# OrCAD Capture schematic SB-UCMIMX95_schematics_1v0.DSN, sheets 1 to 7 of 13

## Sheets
1 01. Index and Block Diagram: title: Index and Block Diagram; rev: 1.0
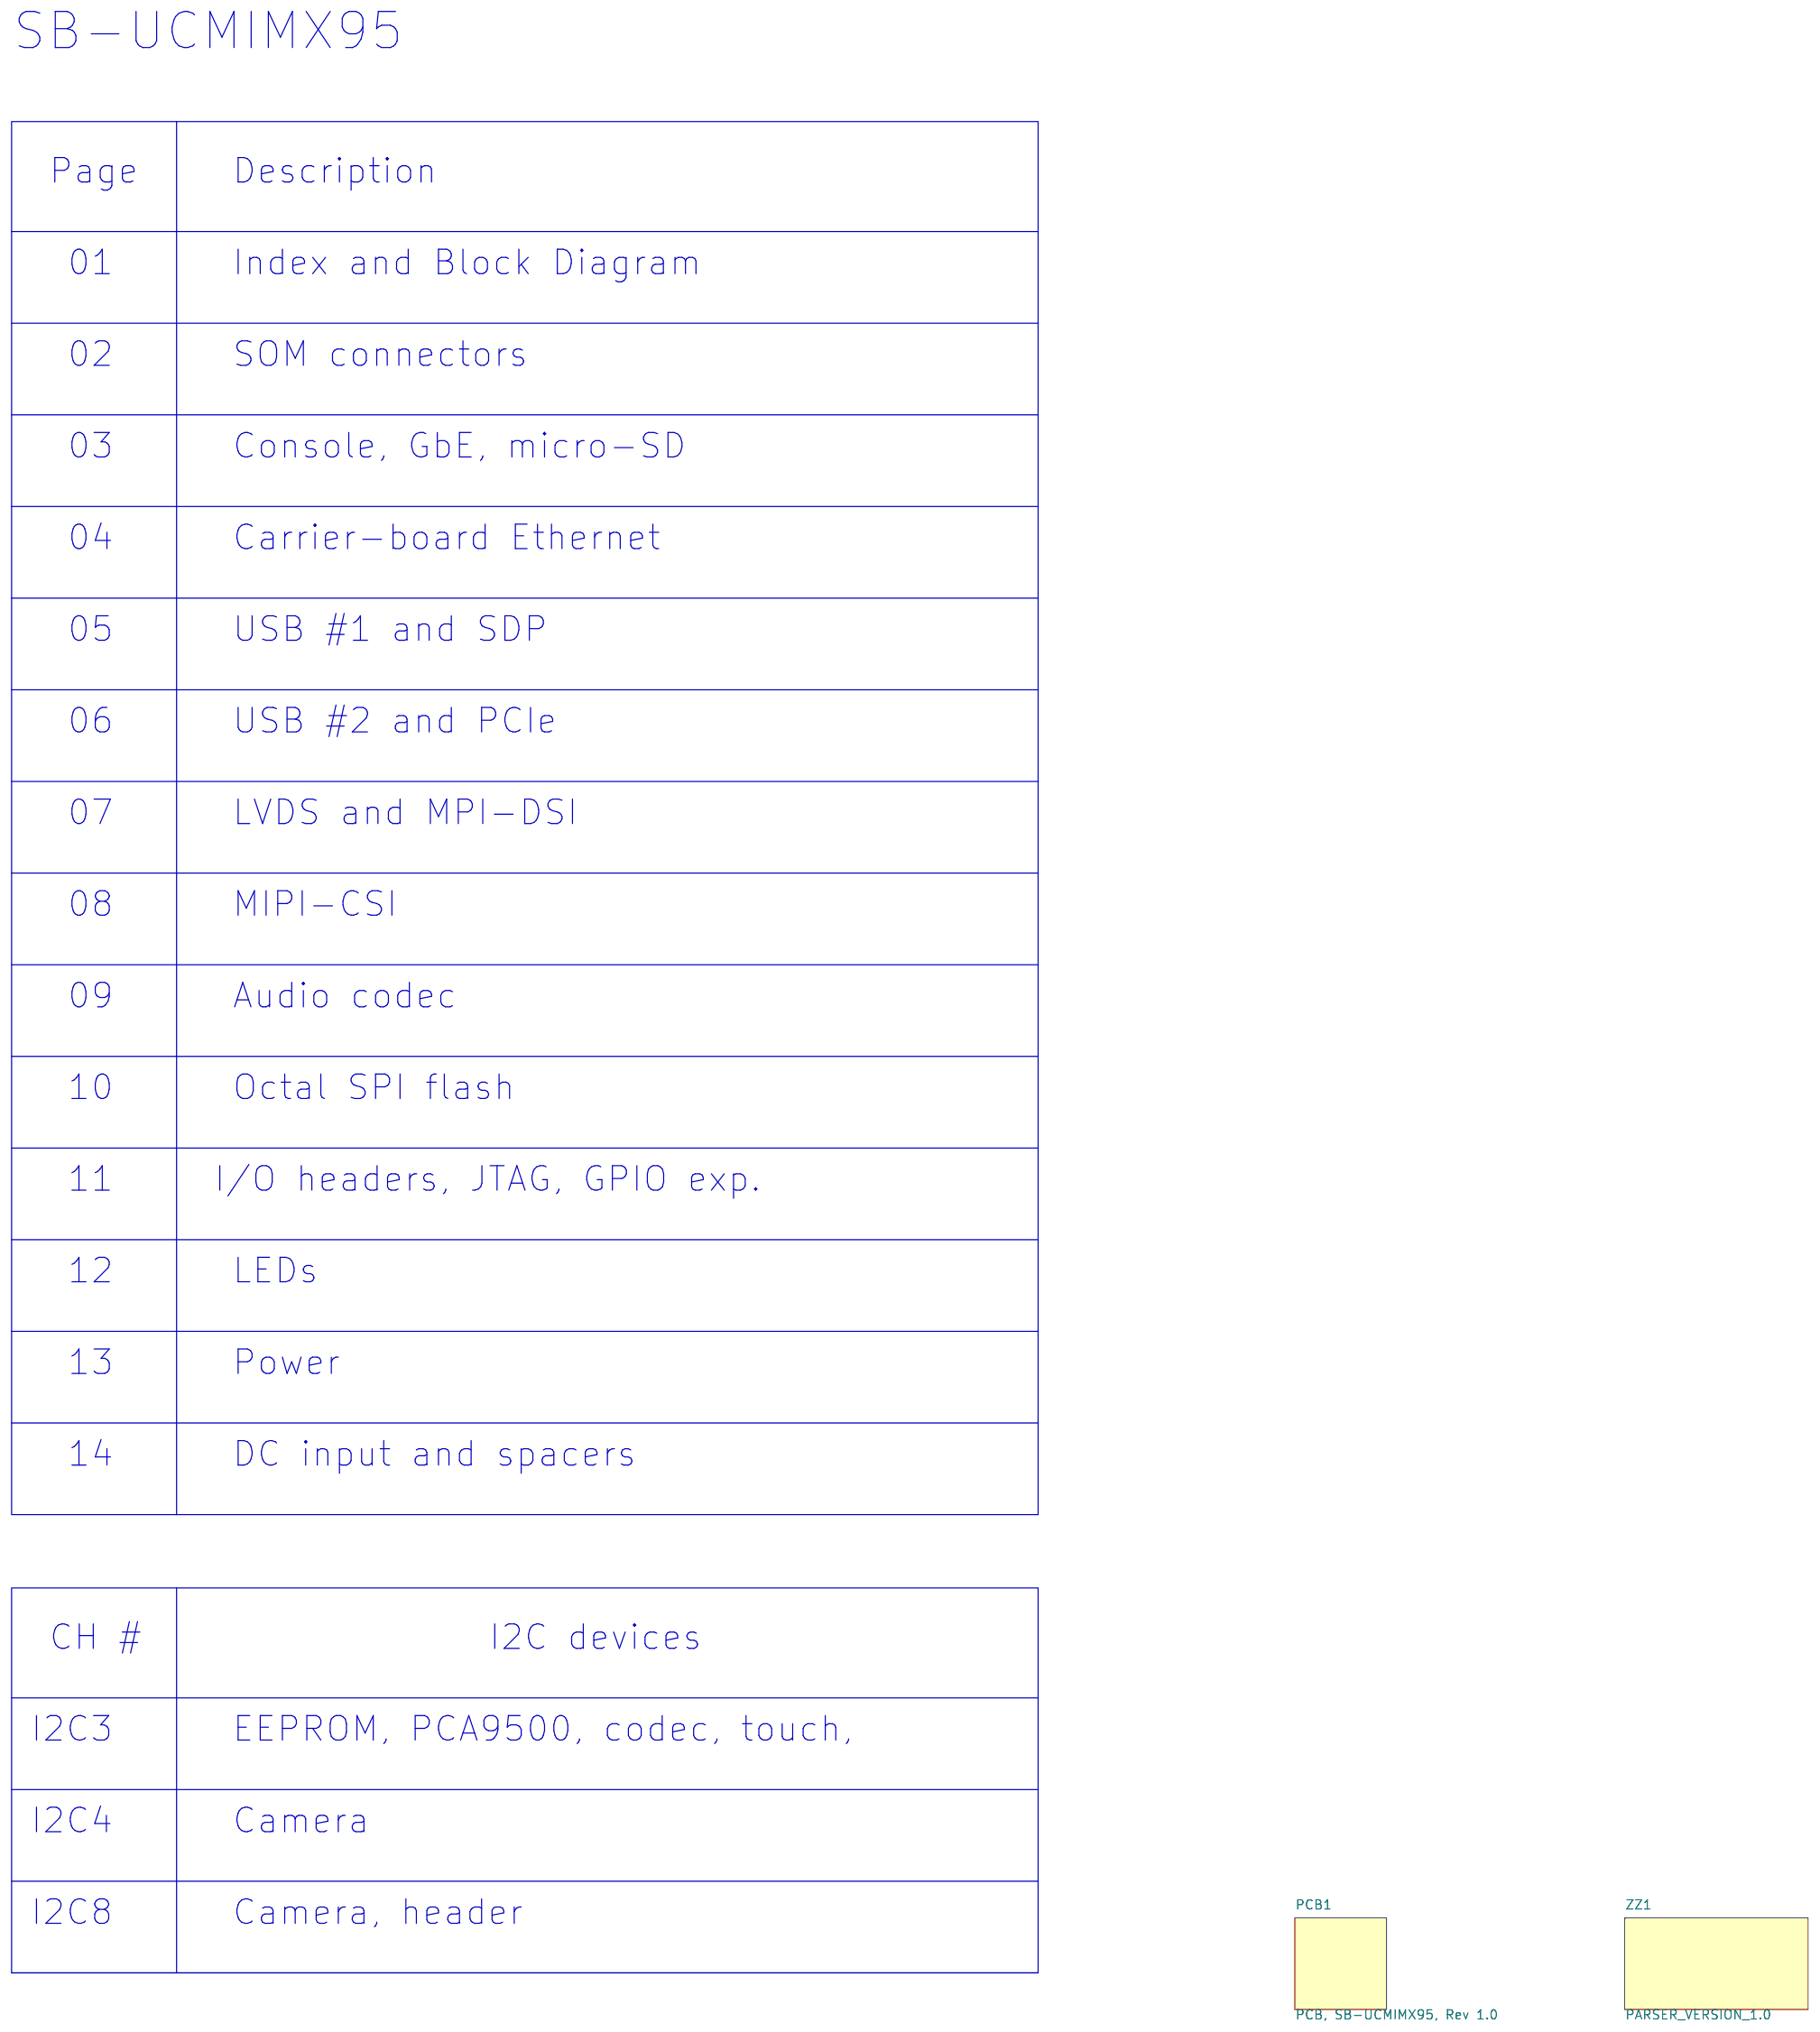
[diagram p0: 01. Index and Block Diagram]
2 02. SOM connectors: size A3; title: SOM connectors
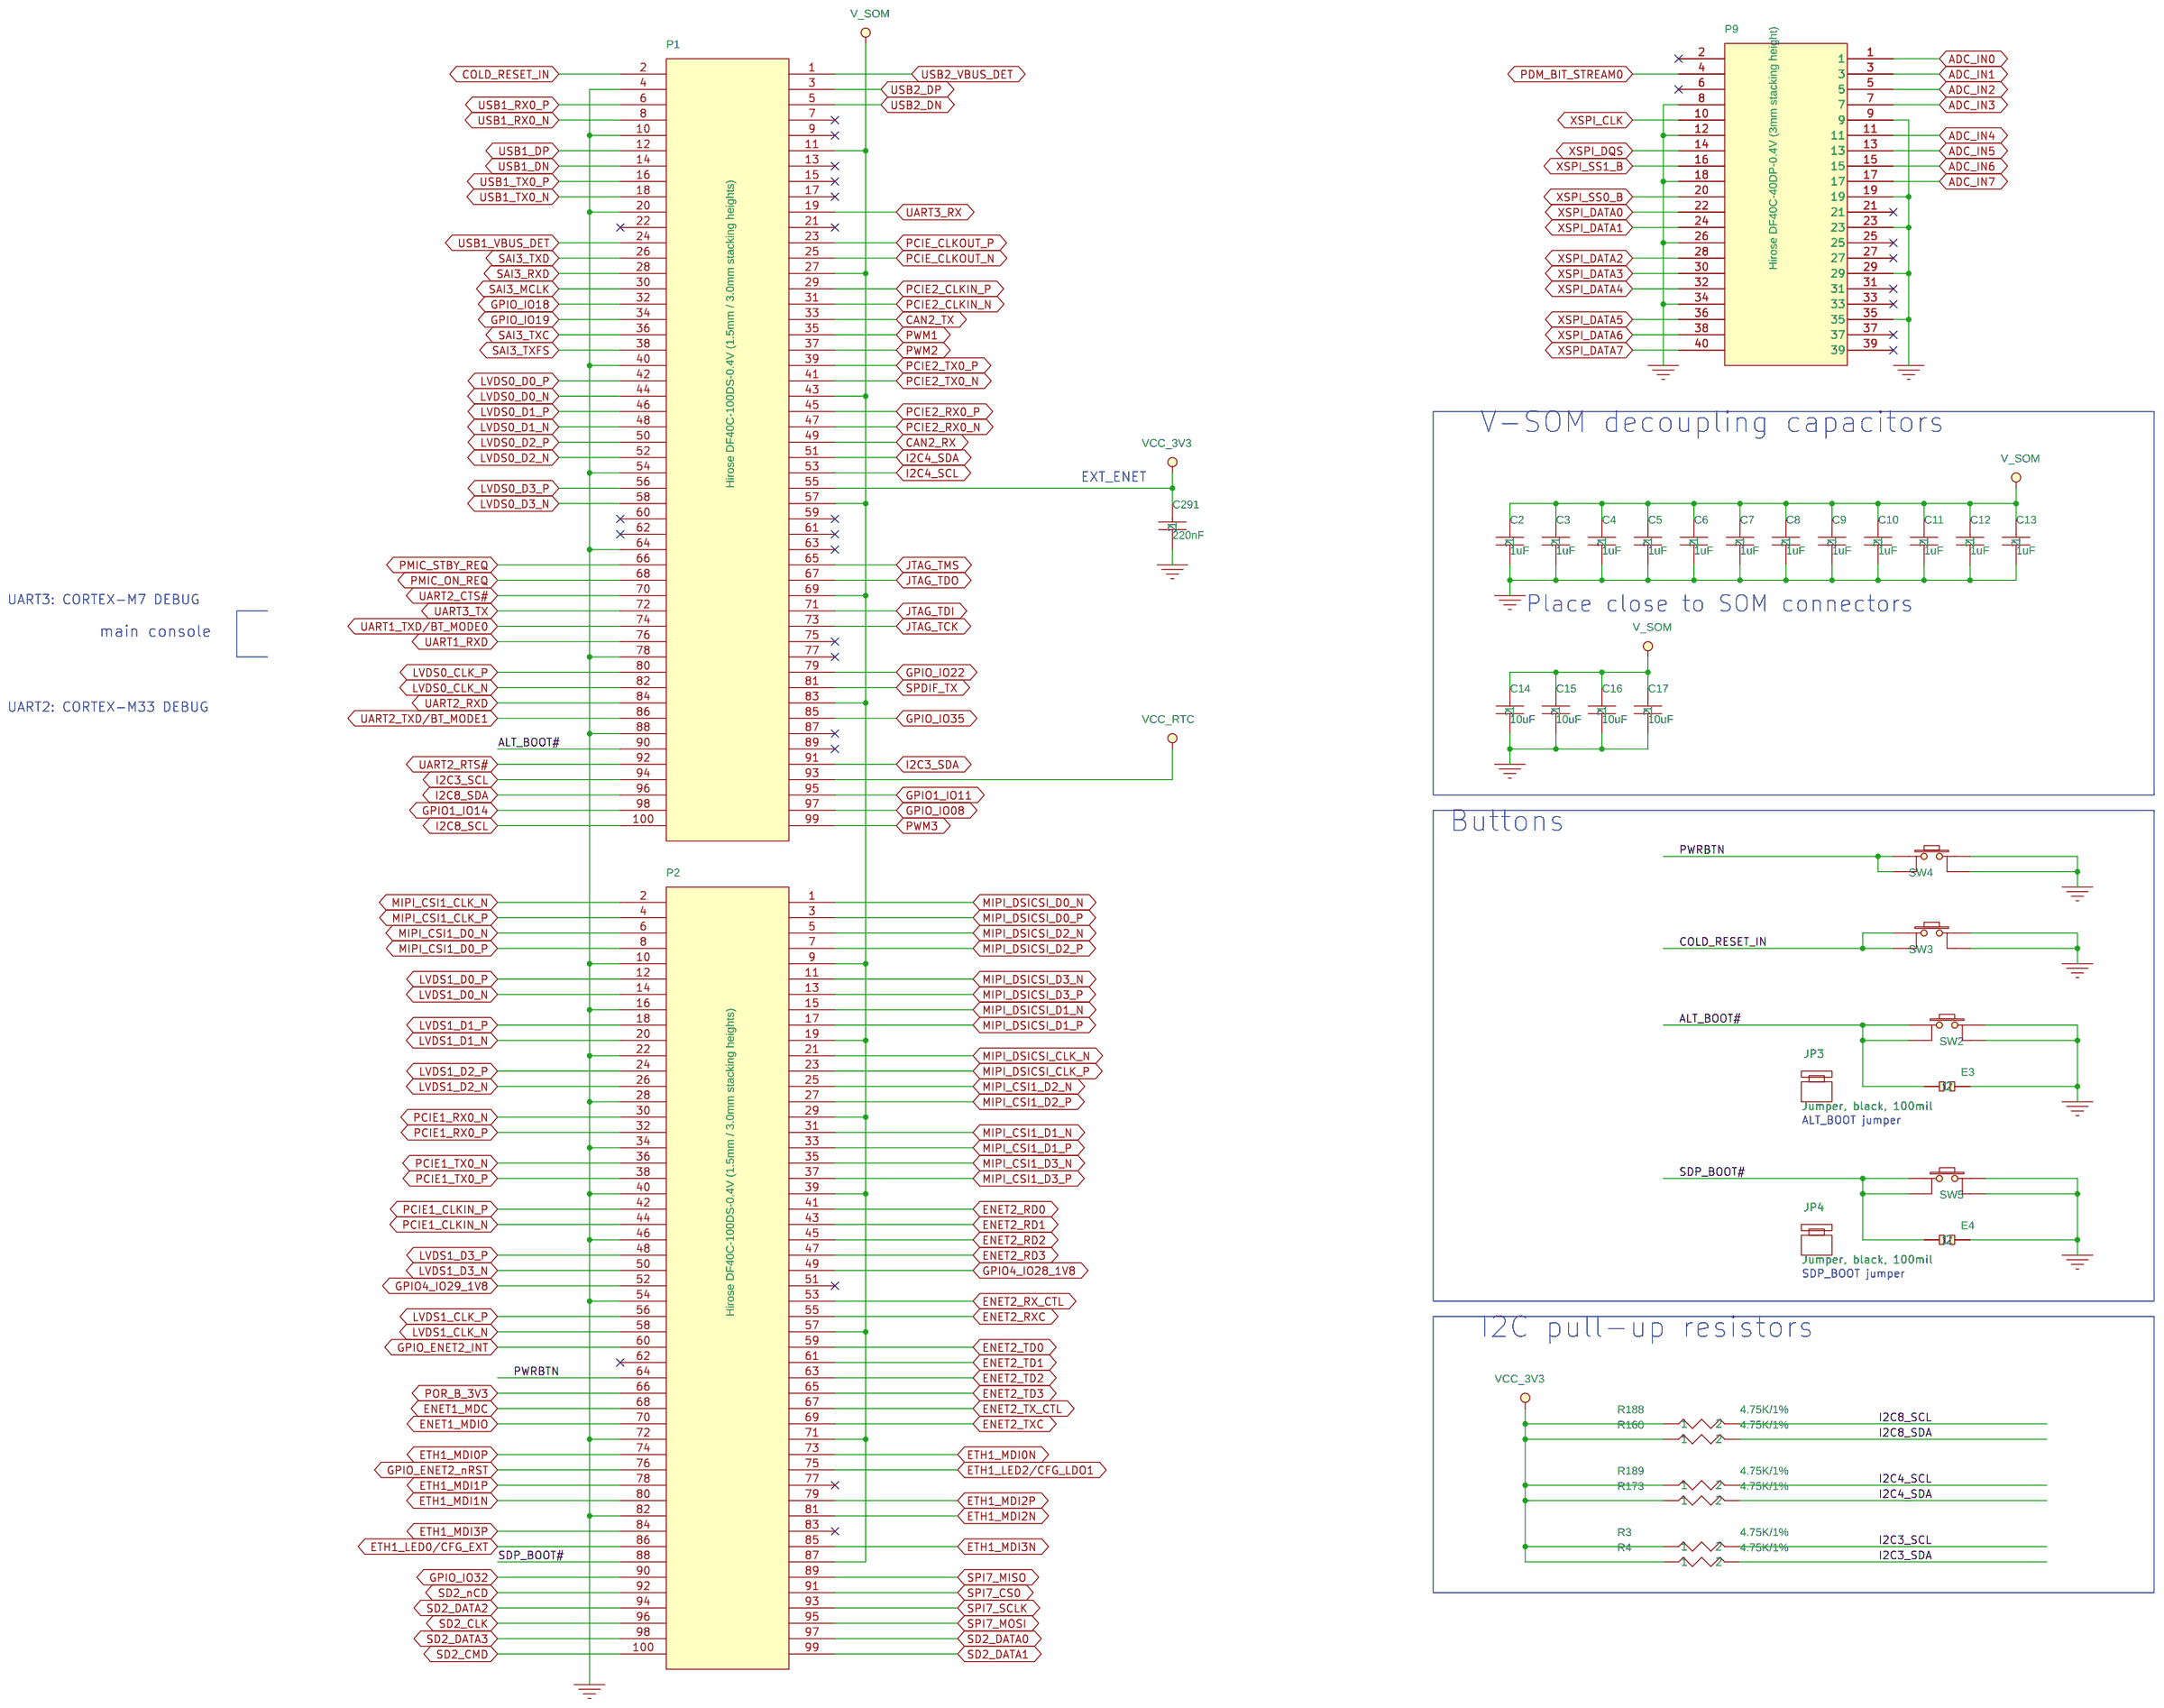
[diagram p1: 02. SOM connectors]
3 03. Console, GbE, micro-SD: size A3; title: Console, GbE, micro-SD
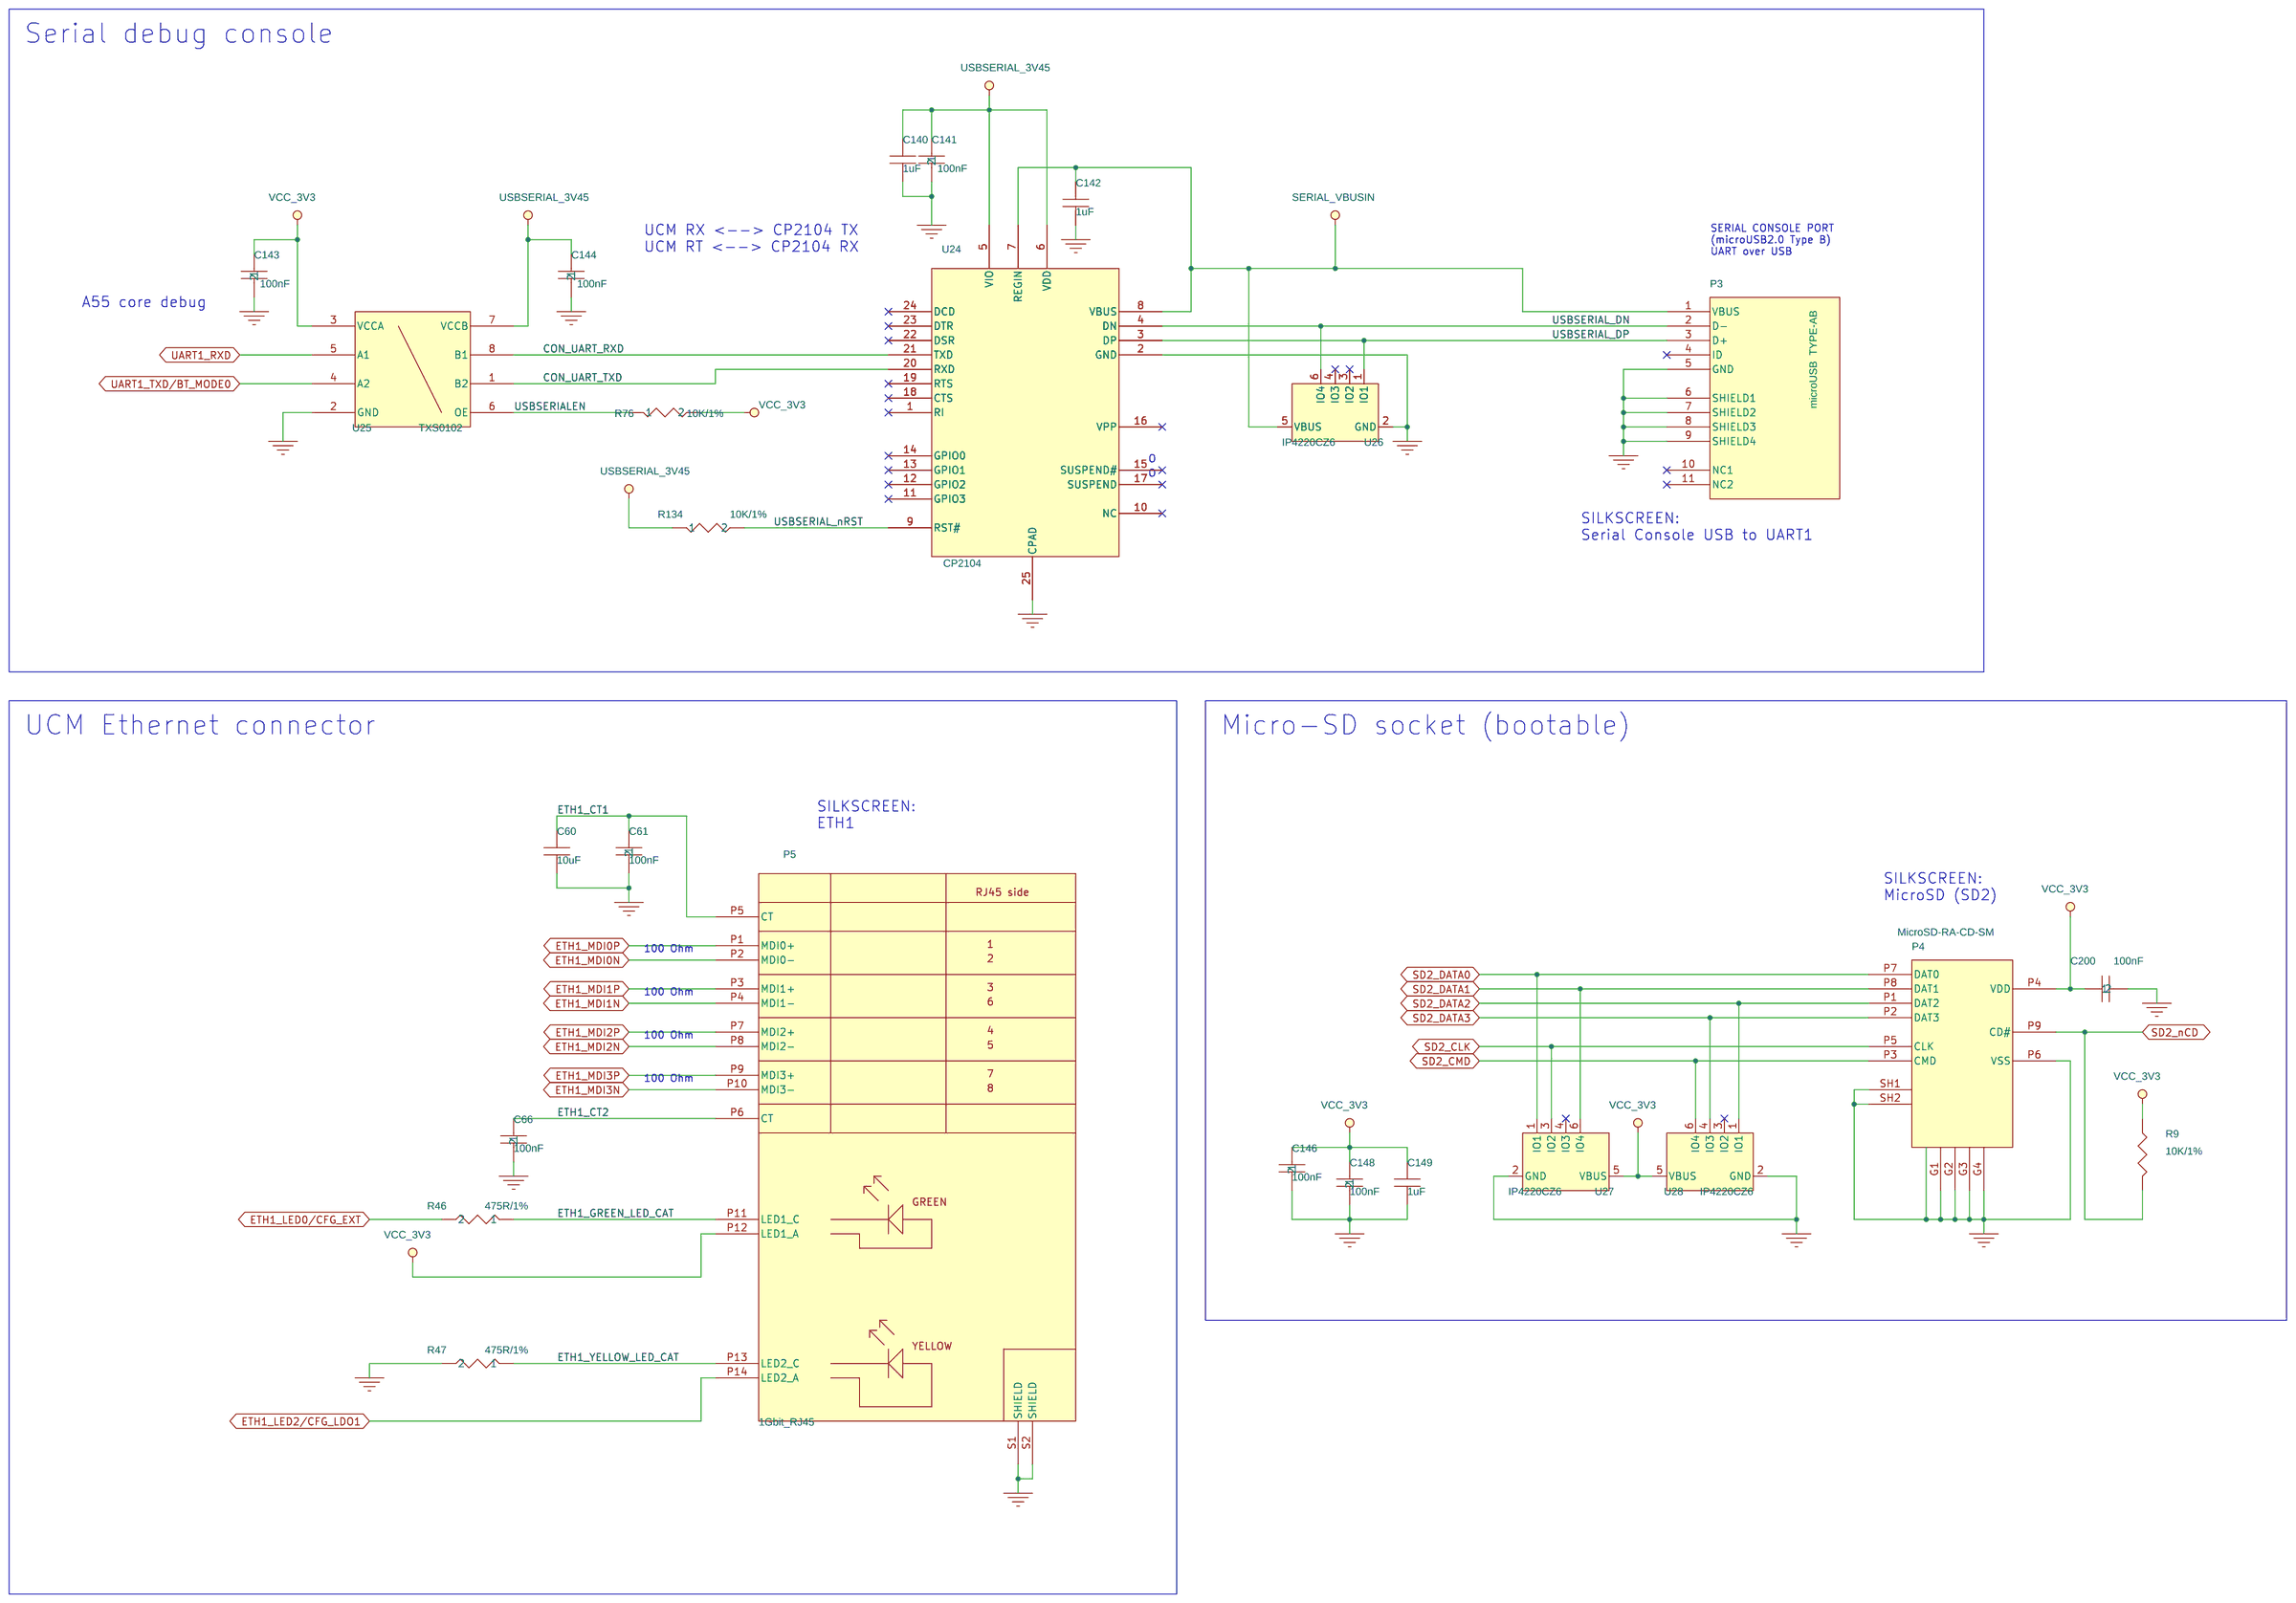
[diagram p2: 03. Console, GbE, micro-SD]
4 04. Carrier-board Ethernet: size A3; title: Carrier-board Ethernet
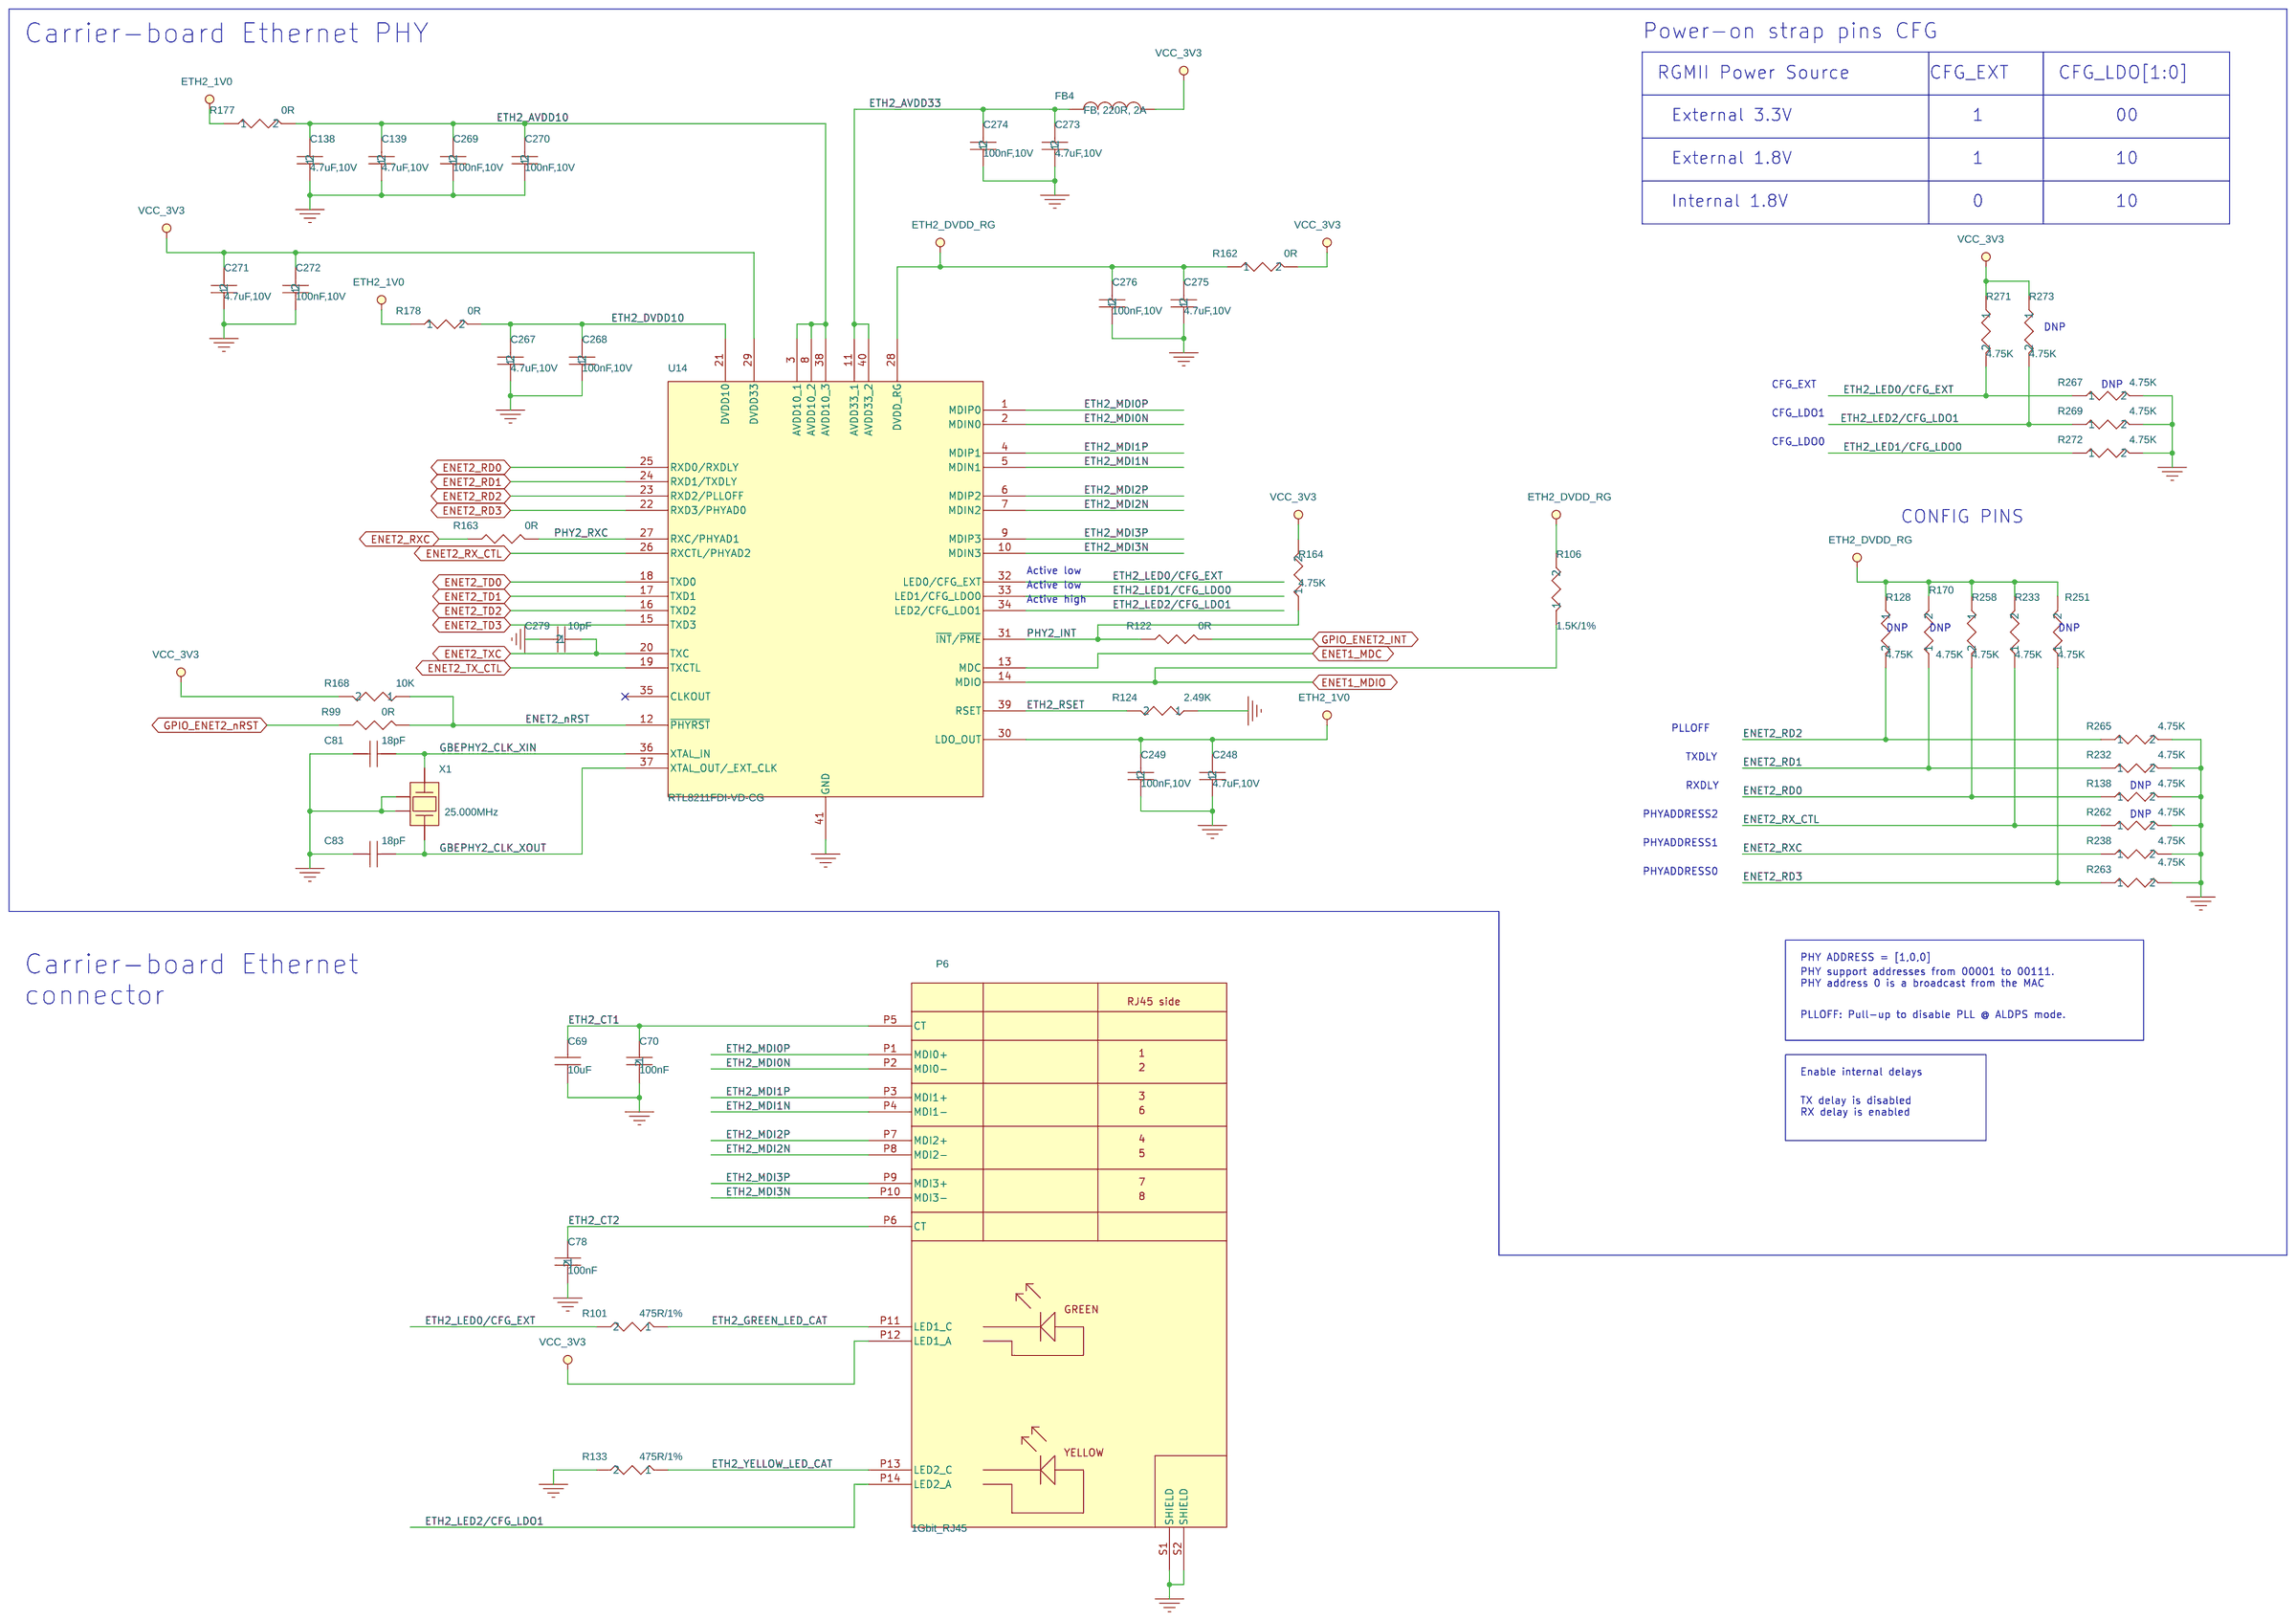
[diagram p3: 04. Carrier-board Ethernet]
5 05. USB #1 and SDP: size A3; title: USB #1 and SDP
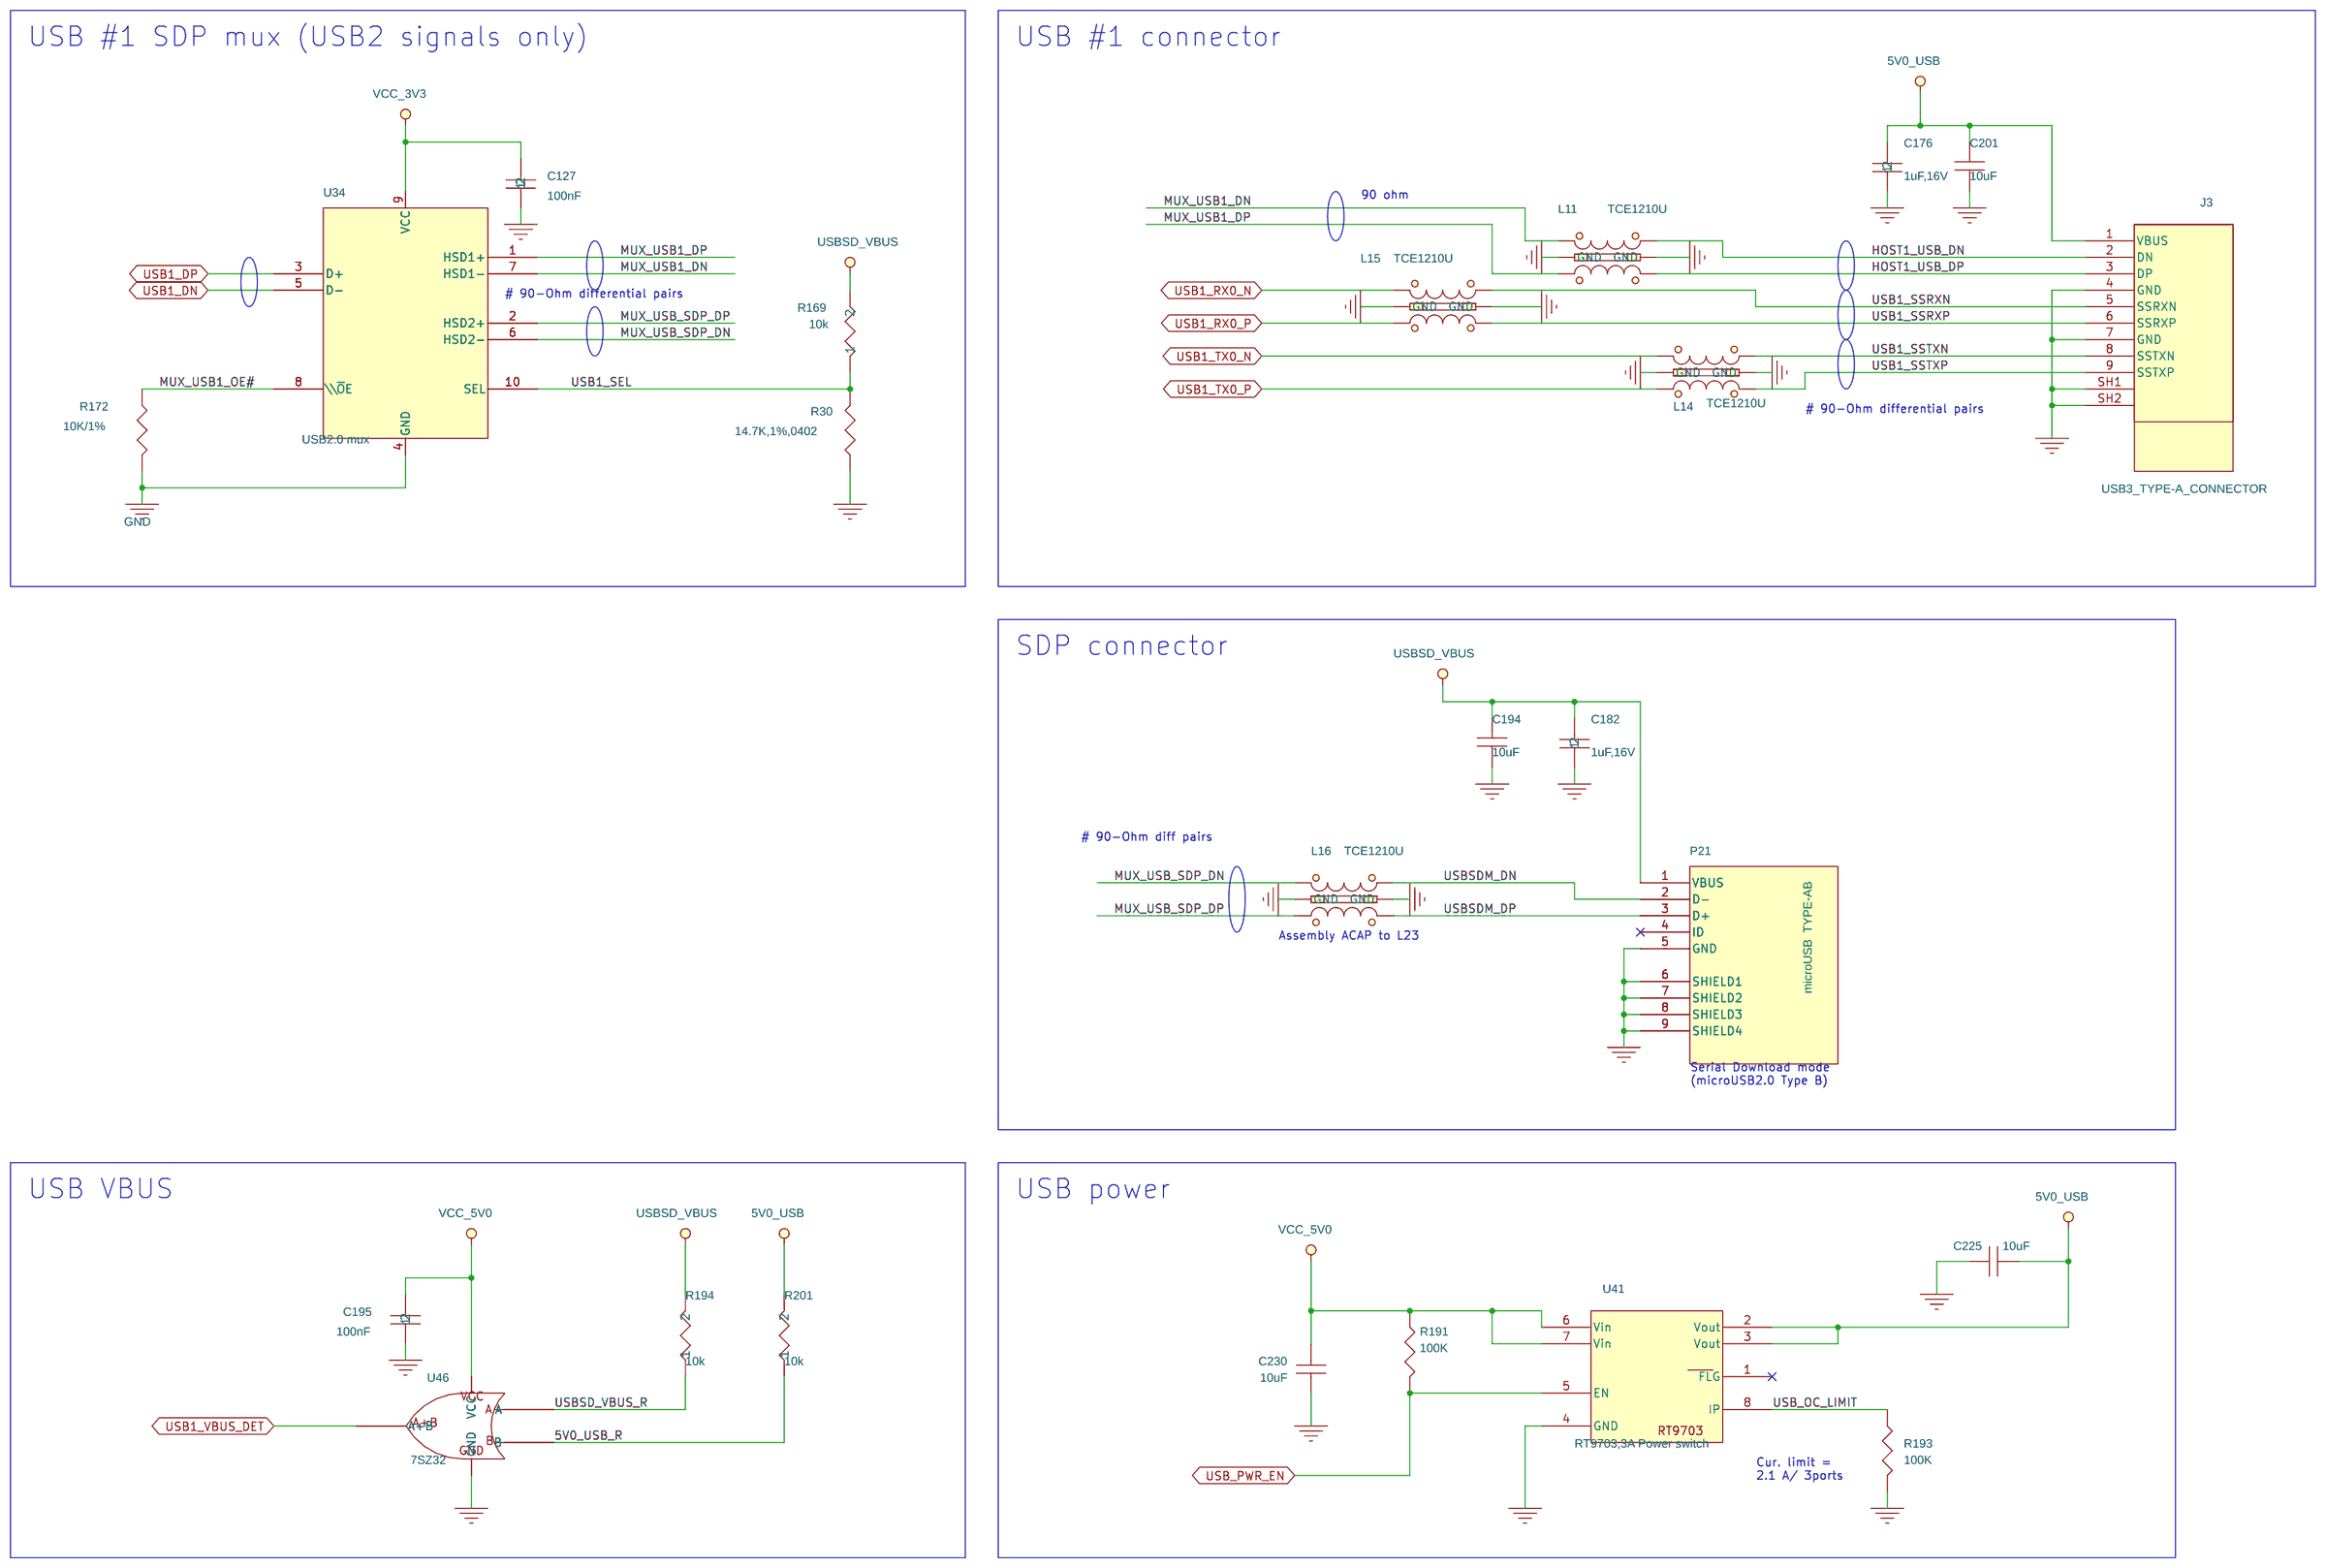
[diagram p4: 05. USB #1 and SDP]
6 06. USB #2 and PCIe: size A3; title: USB #2 and PCIe
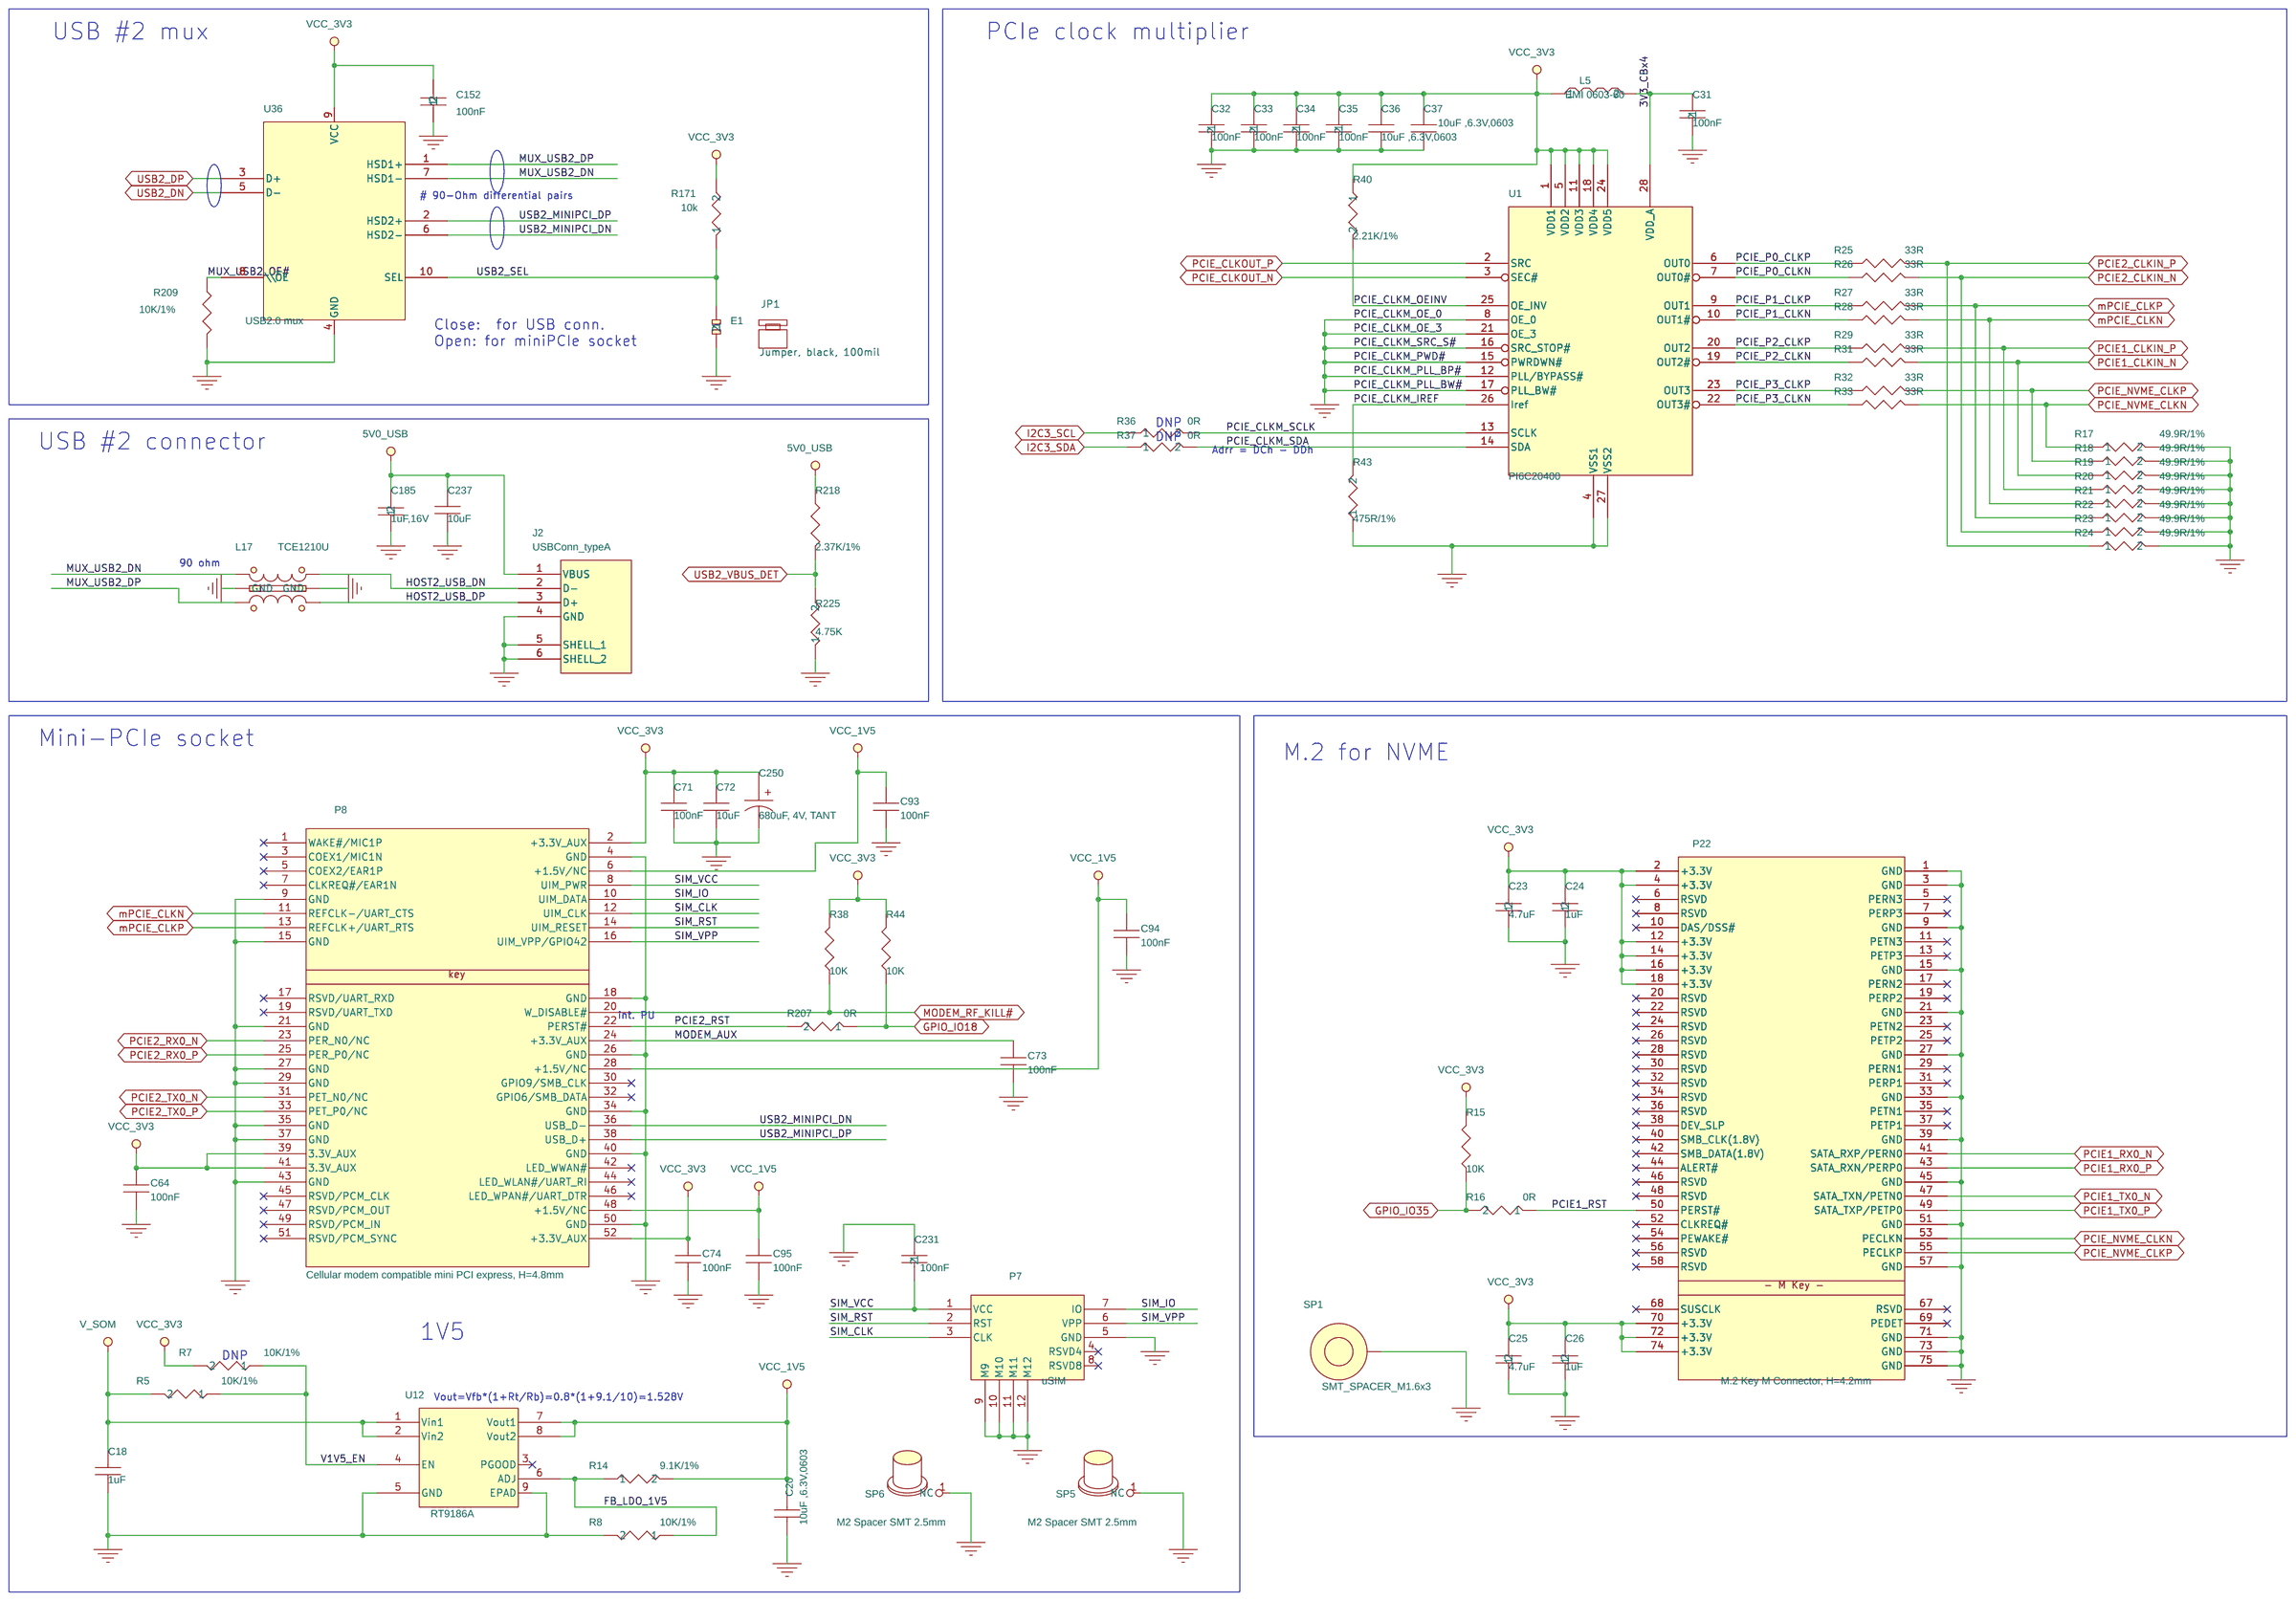
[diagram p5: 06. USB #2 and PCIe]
7 07. LVDS and MIPI-DSI: size A3; title: LVDS and MIPI-DSI
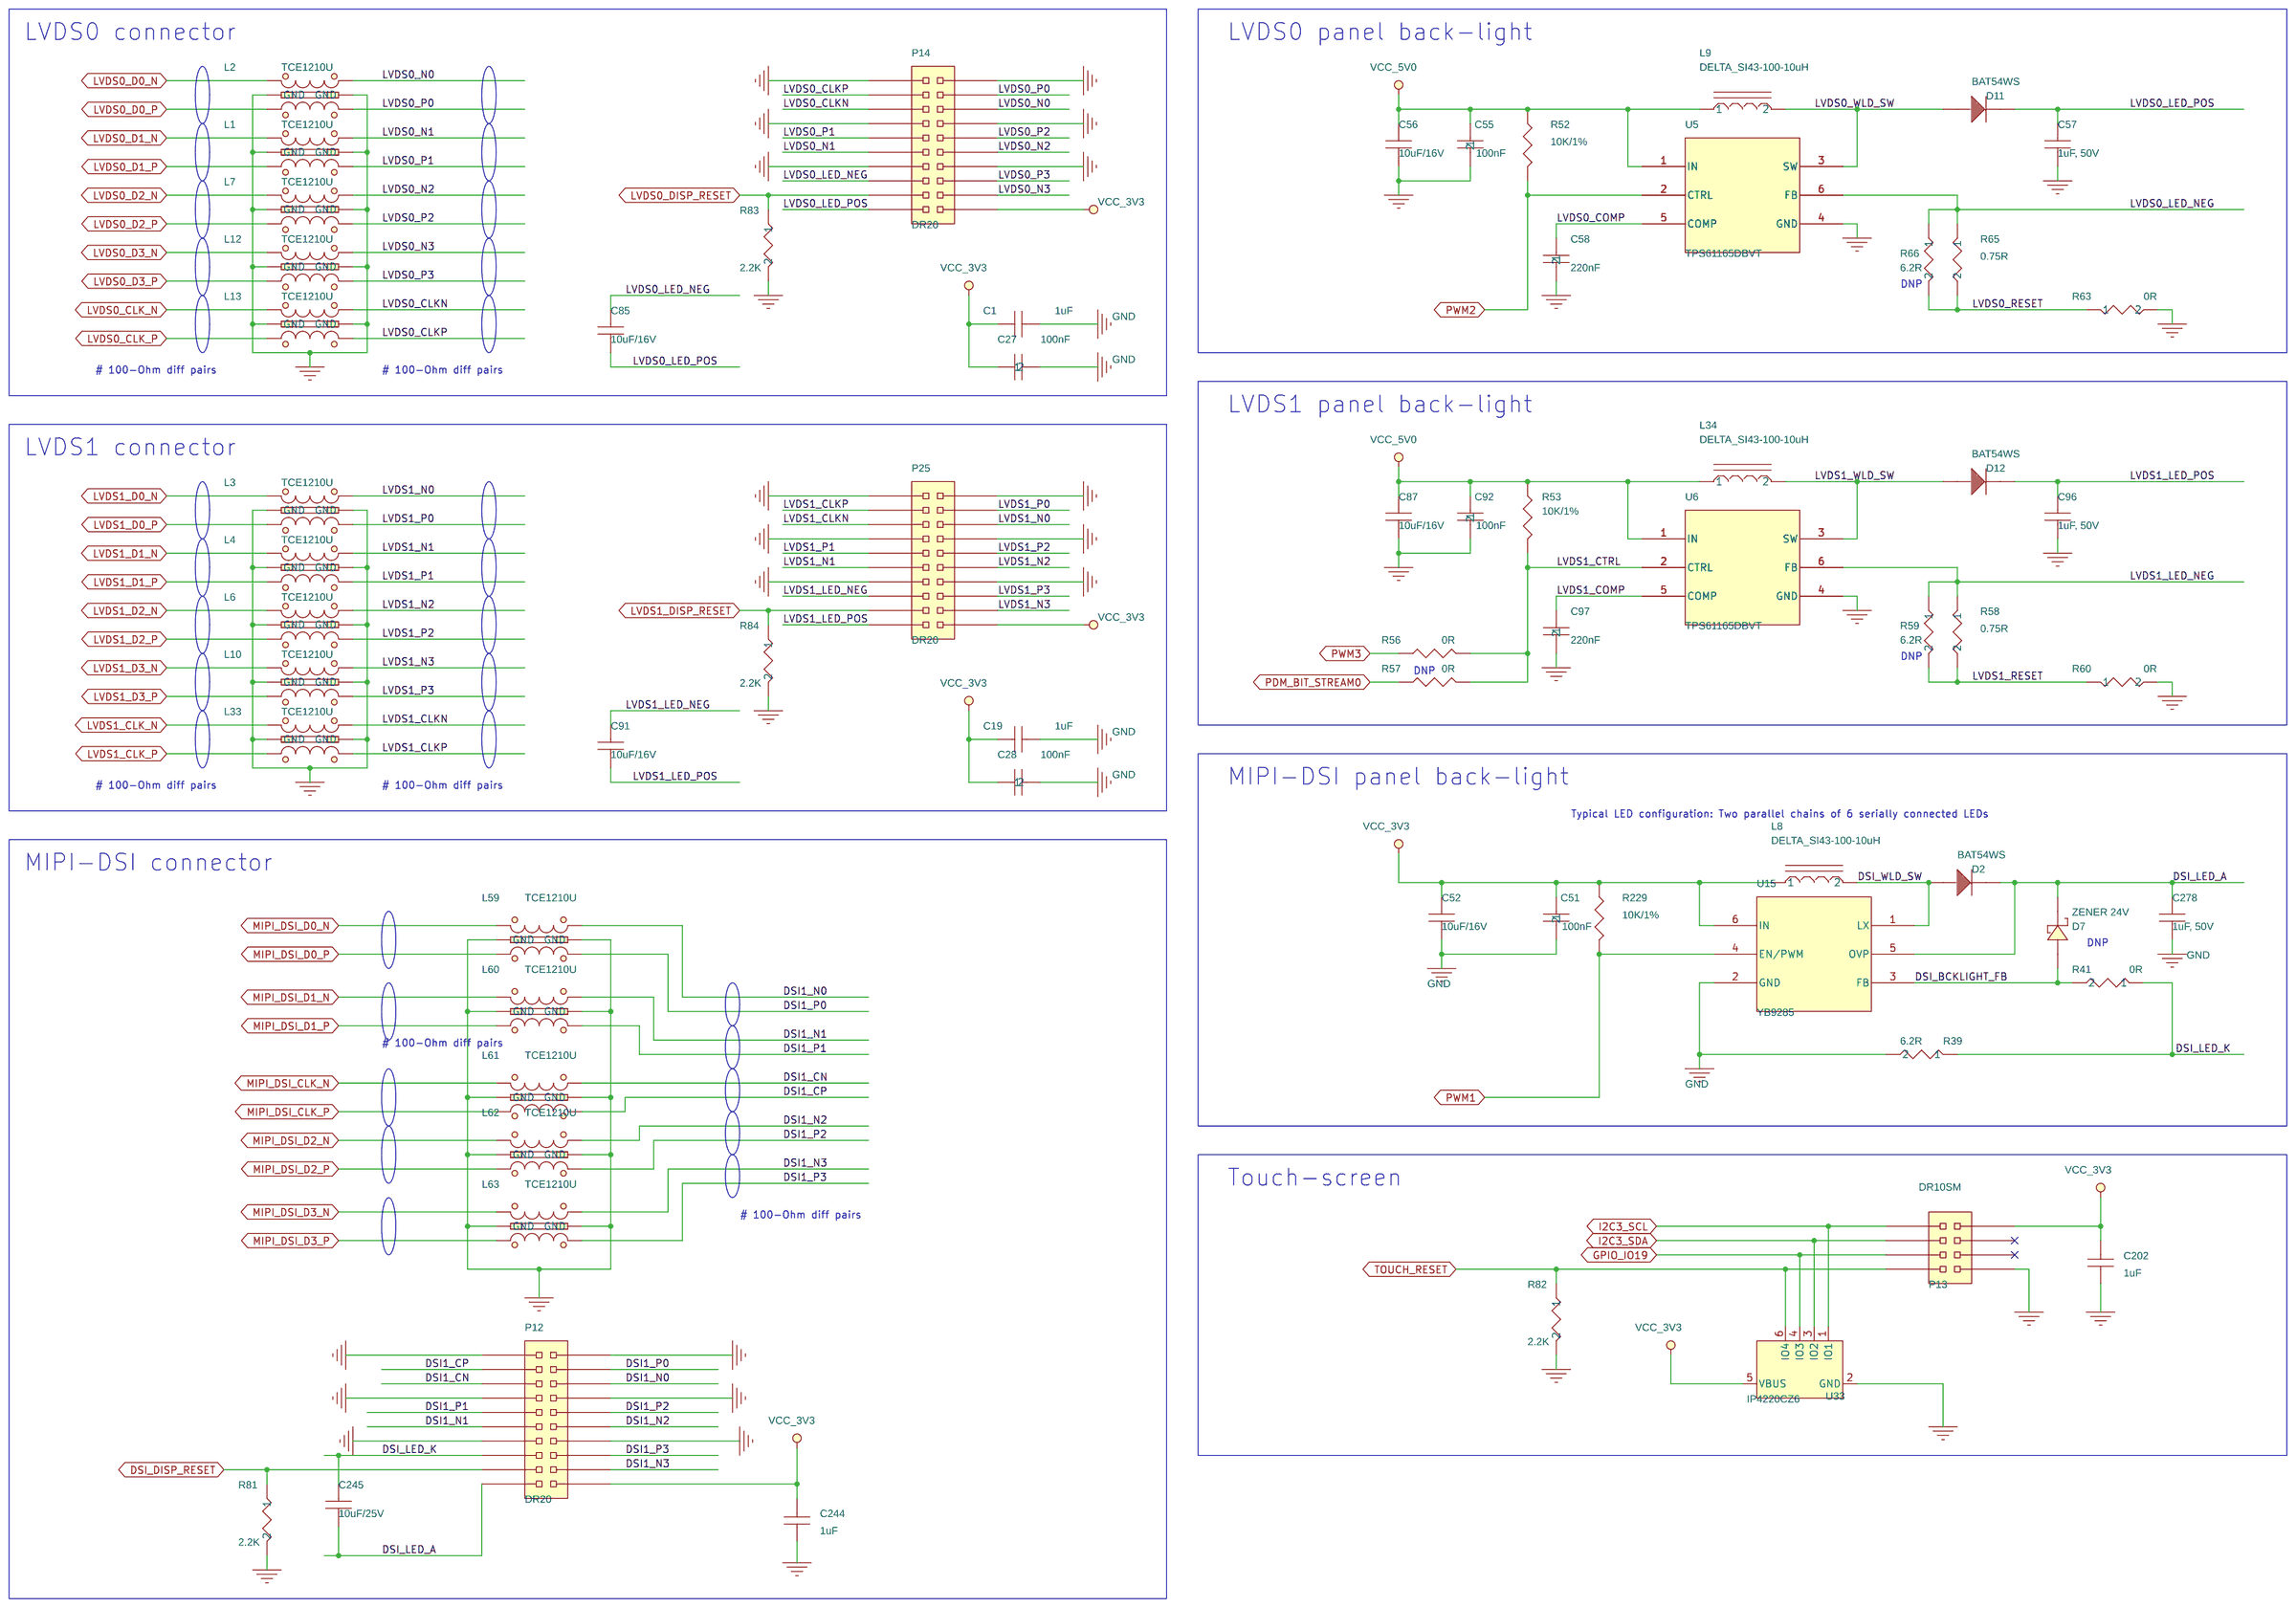
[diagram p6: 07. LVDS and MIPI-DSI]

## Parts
sheet 01. Index and Block Diagram
PCB1  PCB, SB-UCMIMX95, Rev 1.0  [PCB]
ZZ1  PARSER_VERSION_1.0
sheet 02. SOM connectors
C2  1uF  [RC0402]
C3  1uF  [RC0402]
C4  1uF  [RC0402]
C5  1uF  [RC0402]
C6  1uF  [RC0402]
C7  1uF  [RC0402]
C8  1uF  [RC0402]
C9  1uF  [RC0402]
C10  1uF  [RC0402]
C11  1uF  [RC0402]
C12  1uF  [RC0402]
C13  1uF  [RC0402]
C14  10uF  [RC0402]
C15  10uF  [RC0402]
C16  10uF  [RC0402]
C17  10uF  [RC0402]
C291  220nF  [RC0402]
E3  HDR1X2  [1X2THHDR]
E4  HDR1X2  [1X2THHDR]
JP3  Jumper, black, 100mil
JP4  Jumper, black, 100mil
P1  Hirose DF40C-100DS-0.4V (1.5mm / 3.0mm stacking heights)  [B2B04M2X50R]
P2  Hirose DF40C-100DS-0.4V (1.5mm / 3.0mm stacking heights)  [B2B04M2X50R]
P9  Hirose DF40C-40DP-0.4V (3mm stacking height)  [B2B04M2X50P]
R3  4.75K/1%  [RC0402]
R4  4.75K/1%  [RC0402]
R160  4.75K/1%  [RC0402]
R173  4.75K/1%  [RC0402]
R188  4.75K/1%  [RC0402]
R189  4.75K/1%  [RC0402]
SW2  PushB  [TACTSW6x6SM]
SW3  PushB  [TACTSW6x6SM]
SW4  PushB  [TACTSW6x6SM]
SW5  PushB  [TACTSW6x6SM]
sheet 03. Console, GbE, micro-SD
C60  10uF  [RC0603]
C61  100nF  [RC0402]
C66  100nF  [RC0402]
C140  1uF  [RC0402]
C141  100nF  [RC0402]
C142  1uF  [RC0402]
C143  100nF  [RC0402]
C144  100nF  [RC0402]
C146  100nF  [RC0402]
C148  100nF  [RC0402]
C149  1uF  [RC0402]
C200  100nF  [RC0402]
P3  microUSB  TYPE-AB  [MICRO-USB-AB-RA-SM]
P4  MicroSD-RA-CD-SM  [MicroSD-RA-CD-SM]
P5  1Gbit_RJ45  [DUSBRJ-1G]
R9  10K/1%  [RC0402]
R46  475R/1%  [RC0402]
R47  475R/1%  [RC0402]
R76  10K/1%  [RC0402]
R134  10K/1%  [RC0402]
U24  CP2104  [MO-220VGGD-8]
U25  TXS0102  [MO-187DA-8]
U26  IP4220CZ6  [SOT23-6L]
U27  IP4220CZ6  [SOT23-6L]
U28  IP4220CZ6  [SOT23-6L]
sheet 04. Carrier-board Ethernet
C69  10uF  [RC0603]
C70  100nF  [RC0402]
C78  100nF  [RC0402]
C81  18pF  [RC0402]
C83  18pF  [RC0402]
C138  4.7uF,10V  [RC0402]
C139  4.7uF,10V  [RC0402]
C248  4.7uF,10V  [RC0402]
C249  100nF,10V  [RC0402]
C267  4.7uF,10V  [RC0402]
C268  100nF,10V  [RC0402]
C269  100nF,10V  [RC0402]
C270  100nF,10V  [RC0402]
C271  4.7uF,10V  [RC0402]
C272  100nF,10V  [RC0402]
C273  4.7uF,10V  [RC0402]
C274  100nF,10V  [RC0402]
C275  4.7uF,10V  [RC0402]
C276  100nF,10V  [RC0402]
C279  10pF  [RC0402]
FB4  FB, 220R, 2A  [FB0402]
P6  1Gbit_RJ45  [DUSBRJ-1G]
R99  0R  [RC0402]
R101  475R/1%  [RC0402]
R106  1.5K/1%  [RC0402]
R122  0R  [RC0402]
R124  2.49K  [RC0402]
R128  4.75K  [RC0402]
R133  475R/1%  [RC0402]
R138  4.75K  [RC0402]
R162  0R  [RC0402]
R163  0R  [RC0402]
R164  4.75K  [RC0402]
R168  10K  [RC0402]
R170  4.75K  [RC0402]
R177  0R  [RC0402]
R178  0R  [RC0402]
R232  4.75K  [RC0402]
R233  4.75K  [RC0402]
R238  4.75K  [RC0402]
R251  4.75K  [RC0402]
R258  4.75K  [RC0402]
R262  4.75K  [RC0402]
R263  4.75K  [RC0402]
R265  4.75K  [RC0402]
R267  4.75K  [RC0402]
R269  4.75K  [RC0402]
R271  4.75K  [RC0402]
R272  4.75K  [RC0402]
R273  4.75K  [RC0402]
U14  RTL8211FDI-VD-CG  [qfn40_0p4_5x5mm]
X1  25.000MHz  [OSC3225]
sheet 05. USB #1 and SDP
C127  100nF  [RC0402]
C176  1uF,16V  [RC0402]
C182  1uF,16V  [RC0402]
C194  10uF  [C0603-08]
C195  100nF  [RC0402]
C201  10uF  [C0603-08]
C225  10uF  [C0603-08]
C230  10uF  [C0603-08]
J3  USB3_TYPE-A_CONNECTOR  [USB3_TYPEA]
L11  TCE1210U  [EMI1012-ESD]
L14  TCE1210U  [EMI1012-ESD]
L15  TCE1210U  [EMI1012-ESD]
L16  TCE1210U  [EMI1012-ESD]
P21  microUSB  TYPE-AB  [MICRO-USB-AB-RA-SM]
R30  14.7K,1%,0402  [RC0402]
R169  10k  [RC0402]
R172  10K/1%  [RC0402]
R191  100K  [RC0402]
R193  100K  [RC0402]
R194  10k  [RC0402]
R201  10k  [RC0402]
U34  USB2.0 mux  [MO-255U1418E]
U41  RT9703,3A Power switch  [SO-8-150]
U46  7SZ32  [SC70]
sheet 06. USB #2 and PCIe
C18  1uF  [RC0402]
C20  10uF ,6.3V,0603  [C0603-08]
C23  4.7uF  [C0603-08]
C24  1uF  [RC0402]
C25  4.7uF  [C0603-08]
C26  1uF  [RC0402]
C31  100nF  [RC0402]
C32  100nF  [RC0402]
C33  100nF  [RC0402]
C34  100nF  [RC0402]
C35  100nF  [RC0402]
C36  10uF ,6.3V,0603  [RC0603]
C37  10uF ,6.3V,0603  [RC0603]
C64  100nF  [RC0402]
C71  100nF  [RC0402]
C72  10uF  [RC0603]
C73  100nF  [RC0402]
C74  100nF  [RC0402]
C93  100nF  [RC0402]
C94  100nF  [RC0402]
C95  100nF  [RC0402]
C152  100nF  [RC0402]
C185  1uF,16V  [RC0402]
C231  100nF  [RC0402]
C237  10uF  [C0603-08]
C250  680uF, 4V, TANT  [TANT7343]
E1  HDR1X2  [1X2THHDR]
J2  USBConn_typeA  [USB-A-SM]
JP1  Jumper, black, 100mil
L5  EMI 0603-60  [FB0603]
L17  TCE1210U  [EMI1012-ESD]
P7  uSIM  [SKT-MicroSIM6-SM]
P8  Cellular modem compatible mini PCI express, H=4.8mm  [MINIPCIE-4]
P22  M.2 Key M Connector, H=4.2mm  [QFN4x4-32]
R5  10K/1%  [RC0402]
R7  10K/1%  [RC0402]
R8  10K/1%  [RC0402]
R14  9.1K/1%  [RC0402]
R15  10K  [RC0402]
R16  0R  [RC0402]
R17  49.9R/1%  [RC0402]
R18  49.9R/1%  [RC0402]
R19  49.9R/1%  [RC0402]
R20  49.9R/1%  [RC0402]
R21  49.9R/1%  [RC0402]
R22  49.9R/1%  [RC0402]
R23  49.9R/1%  [RC0402]
R24  49.9R/1%  [RC0402]
R25  33R  [RC0402]
R26  33R  [RC0402]
R27  33R  [RC0402]
R28  33R  [RC0402]
R29  33R  [RC0402]
R31  33R  [RC0402]
R32  33R  [RC0402]
R33  33R  [RC0402]
R36  0R  [RC0402]
R37  0R  [RC0402]
R38  10K  [RC0402]
R40  2.21K/1%  [RC0402]
R43  475R/1%  [RC0402]
R44  10K  [RC0402]
R171  10k  [RC0402]
R207  0R  [RC0402]
R209  10K/1%  [RC0402]
R218  2.37K/1%  [RC0402]
R225  4.75K  [RC0402]
SP1  SMT_SPACER_M1.6x3  [MINIPCIE-4-Spacer]
SP5  M2 Spacer SMT 2.5mm  [SpacerM2H4SM]
SP6  M2 Spacer SMT 2.5mm  [SpacerM2H4SM]
U1  PI6C20400  [TSSOP28-6_5-_65]
U12  RT9186A  [DFN3x3-8]
U36  USB2.0 mux  [MO-255U1418E]
sheet 07. LVDS and MIPI-DSI
C1  1uF  [RC0402]
C19  1uF  [RC0402]
C27  100nF  [RC0402]
C28  100nF  [RC0402]
C51  100nF  [RC0402]
C52  10uF/16V  [RC0603]
C55  100nF  [RC0402]
C56  10uF/16V  [RC0603]
C57  1uF, 50V  [RC0603]
C58  220nF  [RC0402]
C85  10uF/16V  [RC0603]
C87  10uF/16V  [RC0603]
C91  10uF/16V  [RC0603]
C92  100nF  [RC0402]
C96  1uF, 50V  [RC0603]
C97  220nF  [RC0402]
C202  1uF  [RC0402]
C244  1uF  [RC0402]
C245  10uF/25V  [RC0603]
C278  1uF, 50V  [RC0603]
D2  BAT54WS  [SOD-323]
D7  ZENER 24V  [SOD-123]
D11  BAT54WS  [SOD-323]
D12  BAT54WS  [SOD-323]
L1  TCE1210U  [EMI1012-ESD]
L2  TCE1210U  [EMI1012-ESD]
L3  TCE1210U  [EMI1012-ESD]
L4  TCE1210U  [EMI1012-ESD]
L6  TCE1210U  [EMI1012-ESD]
L7  TCE1210U  [EMI1012-ESD]
L8  DELTA_SI43-100-10uH  [IND4x4x2_5]
L9  DELTA_SI43-100-10uH  [IND4x4x2_5]
L10  TCE1210U  [EMI1012-ESD]
L12  TCE1210U  [EMI1012-ESD]
L13  TCE1210U  [EMI1012-ESD]
L33  TCE1210U  [EMI1012-ESD]
L34  DELTA_SI43-100-10uH  [IND4x4x2_5]
L59  TCE1210U  [EMI1012-ESD]
L60  TCE1210U  [EMI1012-ESD]
L61  TCE1210U  [EMI1012-ESD]
L62  TCE1210U  [EMI1012-ESD]
L63  TCE1210U  [EMI1012-ESD]
P12  DR20  [2X12THHDR]
P13  DR10SM  [2X4SMHDR]
P14  DR20  [2X12THHDR]
P25  DR20  [2X12THHDR]
R39  6.2R  [RC0402]
R41  0R  [RC0402]
R52  10K/1%  [RC0402]
R53  10K/1%  [RC0402]
R56  0R  [RC0402]
R57  0R  [RC0402]
R58  0.75R  [RC0402]
R59  6.2R  [RC0402]
R60  0R  [RC0402]
R63  0R  [RC0402]
R65  0.75R  [RC0402]
R66  6.2R  [RC0402]
R81  2.2K  [RC0402]
R82  2.2K  [RC0402]
R83  2.2K  [RC0402]
R84  2.2K  [RC0402]
R229  10K/1%  [RC0402]
U5  TPS61165DBVT  [SOT23-6]
U6  TPS61165DBVT  [SOT23-6]
U15  YB9285  [SOT23-6L]
U33  IP4220CZ6  [SOT23-6L]

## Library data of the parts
PCB1 = ATP-FITPC3.rev1.0: CLABCONF0: SB-UCMIMX95; P/N: 188C04550
ZZ1 = PARSER_VERSION_1_1.0: CLABCONF0: DNP
C2 = 100nF,_10V,_X7R,_10%,_0402_1: CLABCONF0: SB-UCMIMX95; P/N: 151B10500S
C3 = 100nF,_10V,_X7R,_10%,_0402_3: CLABCONF0: SB-UCMIMX95; P/N: 151B10500S
C4 = 100nF,_10V,_X7R,_10%,_0402_10: CLABCONF0: SB-UCMIMX95; P/N: 151B10500S
C5 = 100nF,_10V,_X7R,_10%,_0402_4: CLABCONF0: SB-UCMIMX95; P/N: 151B10500S
C6 = 100nF,_10V,_X7R,_10%,_0402_11: CLABCONF0: SB-UCMIMX95; P/N: 151B10500S
C7 = 100nF,_10V,_X7R,_10%,_0402_5: CLABCONF0: SB-UCMIMX95; P/N: 151B10500S
C8 = 100nF,_10V,_X7R,_10%,_0402_8: CLABCONF0: SB-UCMIMX95; P/N: 151B10500S
C9 = 100nF,_10V,_X7R,_10%,_0402_12: CLABCONF0: SB-UCMIMX95; P/N: 151B10500S
C10 = 100nF,_10V,_X7R,_10%,_0402_9: CLABCONF0: SB-UCMIMX95; P/N: 151B10500S
C11 = 100nF,_10V,_X7R,_10%,_0402_7: CLABCONF0: SB-UCMIMX95; P/N: 151B10500S
C12 = 100nF,_10V,_X7R,_10%,_0402_6: CLABCONF0: SB-UCMIMX95; P/N: 151B10500S
C13 = 100nF,_10V,_X7R,_10%,_0402: CLABCONF0: SB-UCMIMX95; P/N: 151B10500S
C14 = 10uF_10V_20%_0402: CLABCONF0: SB-UCMIMX95
C15 = 10uF_10V_20%_0402_3: CLABCONF0: SB-UCMIMX95
C16 = 10uF_10V_20%_0402_2: CLABCONF0: SB-UCMIMX95
C17 = 10uF_10V_20%_0402_1: CLABCONF0: SB-UCMIMX95
C291 = 100nF,_10V,_X7R,_10%,_0402_2: CLABCONF0: SB-UCMIMX95; P/N: 151C22400S
E3 = HDR_1x2_100MIL_TH_JUMPER_1: CLABCONF0: SB-UCMIMX95
E1 E4 = HDR_1x2_100MIL_TH_JUMPER: CLABCONF0: SB-UCMIMX95
JP1 JP3 JP4 = Jumper,_black,_100mil: CLABCONF0: SB-UCMIMX95
P1 P2 = Hirose_DF40C-100DP-0.4V: CLABCONF0: SB-UCMIMX95; P/N: 182K10005S
P9 = Hirose_DF40C-100DP-0_1.4V: CLABCONF0: SB-UCMIMX95; P/N: 182K04005S
R3 = 4_0.75K,1%,0402,1_16W: CLABCONF0: SB-UCMIMX95
R4 = 4_0.75K,1%,0402,1_16W_3: CLABCONF0: SB-UCMIMX95
R160 = 4_0.75K,1%,0402,1_16W_5: CLABCONF0: SB-UCMIMX95
R173 = 4_0.75K,1%,0402,1_16W_1: CLABCONF0: SB-UCMIMX95
R188 = 4_0.75K,1%,0402,1_16W_2: CLABCONF0: SB-UCMIMX95
R189 = 4_0.75K,1%,0402,1_16W_4: CLABCONF0: SB-UCMIMX95
SW2-SW5 = TACT_SW_6x6mm_SMT: CLABCONF0: SB-UCMIMX95
C60 C69 = Cap.,10uF,6.3V,0603,X5R: CLABCONF0: SB-UCMIMX95; P/N: 151B10600S
C61 = 100nF,_10V,_X7R,_10%,_0402_7: CLABCONF0: SB-UCMIMX95
C51 C66 = 100nF,_10V,_X7R,_10%,_0402_6: CLABCONF0: SB-UCMIMX95
C1 C18 C19 C140 C142 C149 C202 C244 = 1uF,X5R,6.3V,0402: CLABCONF0: SB-UCMIMX95
C78 C141 = 100nF,_10V,_X7R,_10%,_0402_1: CLABCONF0: SB-UCMIMX95
C70 C92 C143 = 100nF,_10V,_X7R,_10%,_0402: CLABCONF0: SB-UCMIMX95
C144 = 100nF,_10V,_X7R,_10%,_0402_4: CLABCONF0: SB-UCMIMX95
C28 C146 = 100nF,_10V,_X7R,_10%,_0402_5: CLABCONF0: SB-UCMIMX95
C55 C148 = 100nF,_10V,_X7R,_10%,_0402_3: CLABCONF0: SB-UCMIMX95
C27 C200 C231 = 100nF,_10V,_X7R,_10%,_0402_2: CLABCONF0: SB-UCMIMX95
P3 = Conn_1.,_Micro-USB,_B-Type: CLABCONF0: SB-UCMIMX95; P/N: 180K00501S
P4 = microSD_push-pull: CLABCONF0: SB-UCMIMX95; P/N: 182K01300S
P5 P6 = Con_0.,1GBit_RJ45,_short: CLABCONF0: SB-UCMIMX95
R9 R172 R229 = 10K,1%,0402,1_16W_0: CLABCONF0: SB-UCMIMX95
R43 R46 R133 = 475R_1%,_0402: CLABCONF0: SB-UCMIMX95
R47 R101 = 475R_1%,_0402_1: CLABCONF0: SB-UCMIMX95
R5 R76 = 10K,1%,0402,1_16W_1: CLABCONF0: SB-UCMIMX95
R134 = 10K,1%,0402,1_16W: CLABCONF0: SB-UCMIMX95
U24 = CP2104_1: CLABCONF0: SB-UCMIMX95; P/N: 116A00140S
U25 = TXS0102_0: CLABCONF0: SB-UCMIMX95; P/N: 116A01020S
U26-U28 U33 = IP4220CZ6_0: CLABCONF0: SB-UCMIMX95
C81 C83 = 27pF,_50V,_X7R,_10%,_0402: CLABCONF0: SB-UCMIMX95; P/N: 151D18000S
C138 = 15pF,_50V,_NPO,_5%,_0402_9: CLABCONF0: SB-UCMIMX95; P/N: 151B47500S
C139 = 15pF,_50V,_NPO,_5%,_0402_5: CLABCONF0: SB-UCMIMX95; P/N: 151B47500S
C248 = 15pF,_50V,_NPO,_5%,_0402: CLABCONF0: SB-UCMIMX95; P/N: 151B47500S
C249 = 15pF,_50V,_NPO,_5%,_0402_2: CLABCONF0: SB-UCMIMX95; P/N: 151B10400S
C267 = 15pF,_50V,_NPO,_5%,_0402_13: CLABCONF0: SB-UCMIMX95; P/N: 151B47500S
C268 = 15pF,_50V,_NPO,_5%,_0402_12: CLABCONF0: SB-UCMIMX95; P/N: 151B10400S
C269 = 15pF,_50V,_NPO,_5%,_0402_8: CLABCONF0: SB-UCMIMX95; P/N: 151B10400S
C270 = 15pF,_50V,_NPO,_5%,_0402_7: CLABCONF0: SB-UCMIMX95; P/N: 151B10400S
C271 = 15pF,_50V,_NPO,_5%,_0402_6: CLABCONF0: SB-UCMIMX95; P/N: 151B47500S
C272 = 15pF,_50V,_NPO,_5%,_0402_14: CLABCONF0: SB-UCMIMX95; P/N: 151B10400S
C273 = 15pF,_50V,_NPO,_5%,_0402_4: CLABCONF0: SB-UCMIMX95; P/N: 151B47500S
C274 = 15pF,_50V,_NPO,_5%,_0402_11: CLABCONF0: SB-UCMIMX95; P/N: 151B10400S
C275 = 15pF,_50V,_NPO,_5%,_0402_1: CLABCONF0: SB-UCMIMX95; P/N: 151B47500S
C276 = 15pF,_50V,_NPO,_5%,_0402_10: CLABCONF0: SB-UCMIMX95; P/N: 151B10400S
C279 = 15pF,_50V,_NPO,_5%,_0402_3: CLABCONF0: DNP; P/N: 151D10000S
FB4 = Ferrite_bead_,_120_Ohm@3A: CLABCONF0: SB-UCMIMX95; P/N: 147D22101S
R56 R99 = 0R,_0402_0_1: CLABCONF0: SB-UCMIMX95
R106 = 1.5K_1%,_0402: CLABCONF0: SB-UCMIMX95
R122 = 0R,_0402_0: CLABCONF0: SB-UCMIMX95
R124 = 1M_,5%,_0402_2: CLABCONF0: SB-UCMIMX95; P/N: 161C24911S
R128 = 4.75K,1%,0402,1_16W_7: CLABCONF0: DNP
R138 = 4.75K,1%,0402,1_16W_4: CLABCONF0: DNP
R162 = 0R,_0402_2: CLABCONF0: SB-UCMIMX95
R163 = 0R,_0402_0_2: CLABCONF0: SB-UCMIMX95
R164 R225 = 1M_,5%,_0402: CLABCONF0: SB-UCMIMX95; P/N: 161C47511S
R168 R171 R194 = 1M_,5%,_0402_1: CLABCONF0: SB-UCMIMX95; P/N: 161C10021S
R170 = 4.75K,1%,0402,1_16W_1: CLABCONF0: DNP
R177 R207 = 0R,_0402_1: CLABCONF0: SB-UCMIMX95
R41 R178 = 0R,_0402: CLABCONF0: SB-UCMIMX95
R232 = 4.75K,1%,0402,1_16W: CLABCONF0: SB-UCMIMX95
R233 = 4.75K,1%,0402,1_16W_2: CLABCONF0: SB-UCMIMX95
R238 = 4.75K,1%,0402,1_16W_15: CLABCONF0: SB-UCMIMX95
R251 = 4.75K,1%,0402,1_16W_12: CLABCONF0: DNP
R258 = 4.75K,1%,0402,1_16W_13: CLABCONF0: SB-UCMIMX95
R262 = 4.75K,1%,0402,1_16W_8: CLABCONF0: DNP
R263 = 4.75K,1%,0402,1_16W_14: CLABCONF0: SB-UCMIMX95
R265 = 4.75K,1%,0402,1_16W_10: CLABCONF0: SB-UCMIMX95
R267 = 4.75K,1%,0402,1_16W_9: CLABCONF0: DNP
R269 = 4.75K,1%,0402,1_16W_11: CLABCONF0: SB-UCMIMX95
R271 = 4.75K,1%,0402,1_16W_6: CLABCONF0: SB-UCMIMX95
R272 = 4.75K,1%,0402,1_16W_3: CLABCONF0: SB-UCMIMX95
R273 = 4.75K,1%,0402,1_16W_5: CLABCONF0: DNP
U14 = RTL8211FDI-40P_A_0: IC XCVR ETH INTEGRATED 10/100/1000MBPS RGMII 3.3V/2.5V/1.8V QFN40; 3D_Mechanical_Footprint_File: http://fcl.am.freescale.net/ALLEGRO/step/qfn40_0p4_5x5mm.STEP; AGILE_PN: TMP-CIP-10596; CAD_APPROVED: Yes; CLABCONF0: SB-UCMIMX95; HEIGHT: 0.9MM; MFG_NAME01: REALTEK SEMICONDUCTOR; P/N: 116A00640S; PRE_APN: 312-83499; Package Size: QFN40; ROHS: Yes; Temp Range: -40  °C  +85 °C
X1 = XTAL,_25.000Mhz,_3x5mm: CLABCONF0: SB-UCMIMX95; P/N: 141B25603I
C32 C127 = 100nF,_10V,_X7R,_10%,_0402_1: CLABCONF0: SB-UCMIMX95; Group: LAN2
C176 = 100nF,_10V,_X7R,_10%,_0402_2: CLABCONF0: SB-UCMIMX95; P/N: 151C10500S
C182 = 100nF,_10V,_X7R,_10%,_0402_3: CLABCONF0: SB-UCMIMX95; P/N: 151C10500S
C20 C194 C201 C225 C237 = 10uF,6_0.3V,0603,20%X5R: CLABCONF0: SB-UCMIMX95
C195 = 100nF,_10V,_X7R,_10%,_0402: CLABCONF0: SB-UCMIMX95; Group: LAN2
C230 = 10uF,6.3V,0603,20%,X5R_0: CLABCONF0: SB-UCMIMX95
J3 = USB3_TYPEA_CONNECTER_0: CLABCONF0: SB-UCMIMX95
L1-L4 L6 L7 L10-L17 L33 L59-L63 = ESD_CHOKE_DIFFx2_10: CLABCONF0: SB-UCMIMX95; P/N: 142D11801S
P21 = Conn.,_Micro-USB,_B-Type: CLABCONF0: SB-UCMIMX95; P/N: 180K00501S
R30 = RESISTOR: CLABCONF0: SB-UCMIMX95; P/N: 161C14721S
R169 = 1M_,5%,_0402: CLABCONF0: SB-UCMIMX95; P/N: 161C10021S
R191 R193 = 100K,_0402_0: CLABCONF0: SB-UCMIMX95; P/N: 161C10031S
R201 = 1M_,5%,_0402_2: CLABCONF0: SB-UCMIMX95; P/N: 161C10021S
U34 = USB2_0.0_mux: CLABCONF0: SB-UCMIMX95; P/N: 116A72220S
U41 = RT9703,3A_Power_switch+FLG: CLABCONF0: SB-UCMIMX95; P/N: 124S10080S
U46 = 7SZ32_OR_sgl_SC70: CLABCONF0: SB-UCMIMX95
C23 = 100nF,_10V,_X7R,_10%,_0402_9: CLABCONF0: SB-UCMIMX95; P/N: 151B47500S
C24 = 15pF,_50V,_NPO,_5%,_0402_1: CLABCONF0: SB-UCMIMX95; P/N: 151C10500S
C25 = 100nF,_10V,_X7R,_10%,_0402_6: CLABCONF0: SB-UCMIMX95; P/N: 151B47500S
C26 = 15pF,_50V,_NPO,_5%,_0402: CLABCONF0: SB-UCMIMX95; P/N: 151C10500S
C31 = 100nF,_10V,_X7R,_10%,_0402_5: CLABCONF0: SB-UCMIMX95; Group: LAN2
C33 = 100nF,_10V,_X7R,_10%,_0402_7: CLABCONF0: SB-UCMIMX95; Group: LAN2
C34 = 100nF,_10V,_X7R,_10%,_0402_4: CLABCONF0: SB-UCMIMX95; Group: LAN2
C35 = 100nF,_10V,_X7R,_10%,_0402_8: CLABCONF0: SB-UCMIMX95; Group: LAN2
C36 C87 = 10uF,6.3V,0603,20%X5R_2: CLABCONF0: SB-UCMIMX95
C37 C85 = 10uF,6.3V,0603,20%X5R: CLABCONF0: SB-UCMIMX95
C64 C71 C73 C74 C93-C95 = 100nF,_10V,_X7R,_10%,_0402_0: CLABCONF0: SB-UCMIMX95; Group: LAN2
C72 = 10uF,6.3V,0603,20%X5R_1: CLABCONF0: SB-UCMIMX95; P/N: 151B10610S
C152 = 100nF,_10V,_X7R,_10%,_0402_3: CLABCONF0: SB-UCMIMX95; Group: LAN2
C185 = 100nF,_10V,_X7R,_10%,_0402: CLABCONF0: SB-UCMIMX95; P/N: 151C10500S
C250 = CAPACITOR_POL: CLABCONF0: SB-UCMIMX95; P/N: 154A687D0S
J2 = USB_Conn.,_Fem,_Type_A_,_TH,_RA: CLABCONF0: SB-UCMIMX95
L5 = Ferrit_60R@100Mhz_0.4A_0.3R_DCR: CLABCONF0: SB-UCMIMX95
P7 = uSIM_SOCKET_0: CLABCONF0: SB-UCMIMX95
P8 = Conn.,_Mini-PCIe,_for_SIM5360: CLABCONF0: SB-UCMIMX95; P/N: 182K05203S
P22 = M.2_Key_M_Connector: CLABCONF0: SB-UCMIMX95; P/N: 182K06706S
R7 = 10K,1%,0402,1_16W: CLABCONF0: DNP
R8 = 10K,1%,0402,1_16W_2: CLABCONF0: SB-UCMIMX95
R14 = 953R,1%,0402,1_16W_0: CLABCONF0: SB-UCMIMX95; P/N: 161C91011S
R15 = 10K,1%,0402,1_16W_0_1: CLABCONF0: SB-UCMIMX95; Group: Always
R16 = 0R,_0402_1_1: CLABCONF0: SB-UCMIMX95
R17 = 49.9R_1%,_0402_5: CLABCONF0: SB-UCMIMX95
R18 = 49.9R_1%,_0402_2: CLABCONF0: SB-UCMIMX95
R19 = 49.9R_1%,_0402_6: CLABCONF0: SB-UCMIMX95
R20 = 49.9R_1%,_0402_7: CLABCONF0: SB-UCMIMX95
R21 = 49.9R_1%,_0402_4: CLABCONF0: SB-UCMIMX95
R22 = 49.9R_1%,_0402_3: CLABCONF0: SB-UCMIMX95
R23 = 49.9R_1%,_0402_1: CLABCONF0: SB-UCMIMX95
R24 = 49.9R_1%,_0402: CLABCONF0: SB-UCMIMX95
R25 = 0R,_0402_0_5: CLABCONF0: SB-UCMIMX95; P/N: 161C33R05S
R26 = 0R,_0402_0_7: CLABCONF0: SB-UCMIMX95; P/N: 161C33R05S
R27 = 0R,_0402_0_6: CLABCONF0: SB-UCMIMX95; P/N: 161C33R05S
R28 = 0R,_0402_0_4: CLABCONF0: SB-UCMIMX95; P/N: 161C33R05S
R29 = 0R,_0402_0_3: CLABCONF0: SB-UCMIMX95; P/N: 161C33R05S
R31 = 0R,_0402_0_2: CLABCONF0: SB-UCMIMX95; P/N: 161C33R05S
R32 = 0R,_0402_0_1: CLABCONF0: SB-UCMIMX95; P/N: 161C33R05S
R33 = 0R,_0402_0: CLABCONF0: SB-UCMIMX95; P/N: 161C33R05S
R36 = 0R: CLABCONF0: DNP
R37 = 0R_1: CLABCONF0: DNP
R38 = 10K,1%,0402,1_16W_0_2: CLABCONF0: SB-UCMIMX95; Group: Always
R40 = 2.21k_1%_0402: CLABCONF0: SB-UCMIMX95
R44 = 10K,1%,0402,1_16W_0: CLABCONF0: SB-UCMIMX95; Group: Always
R209 = 10K,1%,0402,1_16W_0_3: CLABCONF0: SB-UCMIMX95
R218 = 2.37K_1%,_0402: CLABCONF0: SB-UCMIMX95
SP1 = SMT_SPACER_M2x3_1: CLABCONF0: SB-UCMIMX95; P/N: 383B54510S
SP5 = Spacer_SMT,_M2,_4mm_1: CLABCONF0: SB-UCMIMX95; P/N: 383B52531S
SP6 = Spacer_SMT,_M2,_4mm_0: CLABCONF0: SB-UCMIMX95; P/N: 383B52531S
U1 = PI6C20400: CLABCONF0: SB-UCMIMX95
U12 = RT9186A,LDO_,2.5-5_0.5V,500mA: CLABCONF0: SB-UCMIMX95
U36 = USB2_1.0_mux: CLABCONF0: SB-UCMIMX95; P/N: 116A72220S
C52 = 10uF,6.3V,0603,20%X5R_3: CLABCONF0: SB-UCMIMX95
C56 = 10uF,6.3V,0603,20%X5R_4: CLABCONF0: SB-UCMIMX95
C57 C96 C278 = 1uF,X5R,6.3V,0402: CLABCONF0: SB-UCMIMX95; P/N: 151D10510S
C58 = 100nF,_10V,_X7R,_10%,_0402_1: CLABCONF0: SB-UCMIMX95; P/N: 151C22400S
C91 = 10uF,6.3V,0603,20%X5R_1: CLABCONF0: SB-UCMIMX95
C97 = 100nF,_10V,_X7R,_10%,_0402_4: CLABCONF0: SB-UCMIMX95; P/N: 151C22400S
C245 = 10uF,6_0.3V,0603,20%X5R: CLABCONF0: SB-UCMIMX95; P/N: 151C10611S
D2 D11 D12 = BAT54WS_0: CLABCONF0: SB-UCMIMX95
D7 = ZENER_24V_500mW_SOD-123: CLABCONF0: DNP
L8 = INC_DELTA_SI43-100,_10uH_2: CLABCONF0: SB-UCMIMX95; CLABCONF1: <null>
L9 = INC_DELTA_SI43-100,_10uH: CLABCONF0: SB-UCMIMX95; CLABCONF1: <null>
L34 = INC_DELTA_SI43-100,_10uH_1: CLABCONF0: SB-UCMIMX95; CLABCONF1: <null>
P12 P14 P25 = HDR_2x12_100MIL_0: CLABCONF0: SB-UCMIMX95; P/N: 190C02000S
P13 = HDR_2x5_100MIL_SMT_2: CLABCONF0: SB-UCMIMX95; P/N: 190C00801S
R39 = 2.2R,5%,0402,1_16W_6: CLABCONF0: SB-UCMIMX95; P/N: 161C06R25S
R52 = 10K,1%,0402,1_16W_0_1: CLABCONF0: SB-UCMIMX95
R53 = 10K,1%,0402,1_16W_0_2: CLABCONF0: SB-UCMIMX95
R57 = 0R,_0402_0: CLABCONF0: DNP
R58 = 2.2R,5%,0402,1_16W_5: CLABCONF0: SB-UCMIMX95; P/N: 161C0R751S
R59 = 2.2R,5%,0402,1_16W: CLABCONF0: DNP; P/N: 161C06R25S
R60 = 2.2R,5%,0402,1_16W_1: CLABCONF0: SB-UCMIMX95; P/N: 161C00005S
R63 = 2.2R,5%,0402,1_16W_4: CLABCONF0: SB-UCMIMX95; P/N: 161C00005S
R65 = 2.2R,5%,0402,1_16W_2: CLABCONF0: SB-UCMIMX95; P/N: 161C0R751S
R66 = 2.2R,5%,0402,1_16W_3: CLABCONF0: DNP; P/N: 161C06R25S
R81 = 2.2K,5%,0402.1_16W: CLABCONF0: SB-UCMIMX95
R82 = 2.2K,5%,0402.1_16W_3: CLABCONF0: SB-UCMIMX95
R83 = 2.2K,5%,0402.1_16W_1: CLABCONF0: SB-UCMIMX95
R84 = 2.2K,5%,0402.1_16W_2: CLABCONF0: SB-UCMIMX95
U5 U6 = TPS61165DBVT: CLABCONF0: SB-UCMIMX95; P/N: 123C15100S
U15 = AIC1647_0: CLABCONF0: SB-UCMIMX95; P/N: 123C40000S

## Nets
3V3_CBx4: C31.1 L5.2 U1.28(VDD_A)
5V0_USB: C176.2 C185.2 C201.1 C225.2 C237.1 J2.1(VBUS) J3.1(VBUS) R201.2 R218.1 U41.2(Vout) U41.3(Vout)
5V0_USB_R: R201.1 U46.2(B)
GND: C1.2 C2.2 C3.2 C4.2 C5.2 C6.2 C7.2 C8.2 C9.2 C10.2 C11.2 C12.2 C13.2 C14.2 C15.2 C16.2 C17.2 C18.2 C19.2 C20.2 C23.1 C24.1 C25.1 C26.1 C27.2 C28.2 C31.2 C32.2 C33.2 C34.2 C35.2 C36.2 C37.2 C51.2 C52.2 C55.2 C56.2 C57.2 C58.2 C60.2 C61.2 C64.2 C66.2 C69.2 C70.2 C71.2 C72.2 C73.2 C74.2 C78.2 C81.1 C83.1 C87.2 C92.2 C93.2 C94.2 C95.2 C96.2 C97.2 C127.1 C138.1 C139.1 C140.2 C141.2 C142.2 C143.2 C144.2 C146.2 C148.2 C149.2 C152.1 C176.1 C182.1 C185.1 C194.2 C195.1 C200.2 C201.2 C202.1 C225.1 C230.1 C231.1 C237.2 C244.1 C248.1 C249.1 C250.2 C267.1 C268.1 C269.1 C270.1 C271.1 C272.1 C273.1 C274.1 C275.1 C276.1 C278.2 C279.2 C291.2 E1.2 E3.2 E4.2 J2.4(GND) J2.5(SHELL_1) J2.6(SHELL_2) J3.4(GND) J3.7(GND) J3.SH1 J3.SH2 L1.5(GND) L1.6(GND) L2.5(GND) L2.6(GND) L3.5(GND) L3.6(GND) L4.5(GND) L4.6(GND) L6.5(GND) L6.6(GND) L7.5(GND) L7.6(GND) L10.5(GND) L10.6(GND) L11.5(GND) L11.6(GND) L12.5(GND) L12.6(GND) L13.5(GND) L13.6(GND) L14.5(GND) L14.6(GND) L15.5(GND) L15.6(GND) L16.5(GND) L16.6(GND) L17.5(GND) L17.6(GND) L33.5(GND) L33.6(GND) L59.5(GND) L59.6(GND) L60.5(GND) L60.6(GND) L61.5(GND) L61.6(GND) L62.5(GND) L62.6(GND) L63.5(GND) L63.6(GND) P1.4 P1.10 P1.20 P1.40 P1.54 P1.64 P1.78 P1.88 P2.10 P2.16 P2.22 P2.28 P2.34 P2.40 P2.46 P2.54 P2.72 P2.82 P3.5(GND) P3.6(SHIELD1) P3.7(SHIELD2) P3.8(SHIELD3) P3.9(SHIELD4) P4.G1 P4.G2 P4.G3 P4.G4 P4.P6(VSS) P4.SH1 P4.SH2 P5.S1(SHIELD) P5.S2(SHIELD) P6.S1(SHIELD) P6.S2(SHIELD) P7.5(GND) P7.9(M9) P7.10(M10) P7.11(M11) P7.12(M12) P8.4(GND) P8.9(GND) P8.15(GND) P8.18(GND) P8.21(GND) P8.26(GND) P8.27(GND) P8.29(GND) P8.34(GND) P8.35(GND) P8.37(GND) P8.40(GND) P8.43(GND) P8.50(GND) P9.8 P9.9 P9.12 P9.18 P9.19 P9.23 P9.26 P9.29 P9.34 P9.35 P12.1 P12.2 P12.7 P12.8 P12.13 P12.14 P13.8 P14.1 P14.2 P14.7 P14.8 P14.13 P14.14 P21.5(GND) P21.6(SHIELD1) P21.7(SHIELD2) P21.8(SHIELD3) P21.9(SHIELD4) P22.1(GND) P22.3(GND) P22.9(GND) P22.15(GND) P22.21(GND) P22.27(GND) P22.33(GND) P22.39(GND) P22.45(GND) P22.51(GND) P22.57(GND) P22.71(GND) P22.73(GND) P22.75(GND) P25.1 P25.2 P25.7 P25.8 P25.13 P25.14 R8.2 R17.2 R18.2 R19.2 R20.2 R21.2 R22.2 R23.2 R24.2 R30.2 R39.2 R43.1 R47.2 R60.2 R63.2 R81.2 R82.2 R83.2 R84.2 R124.1 R133.2 R138.2 R172.1 R193.2 R209.1 R225.1 R232.2 R238.2 R262.2 R263.2 R265.2 R267.2 R269.2 R272.2 SP1.NC(1) SP5.1(NC) SP6.1(NC) SW2.1 SW2.3 SW3.1 SW3.3 SW4.1 SW4.3 SW5.1 SW5.3 U1.4(VSS1) U1.8(OE_0) U1.12(PLL/BYPASS#) U1.15(PWRDWN#) U1.16(SRC_STOP#) U1.17(PLL_BW#) U1.21(OE_3) U1.27(VSS2) U5.4(GND) U6.4(GND) U12.5(GND) U12.9(EPAD) U14.41(GND) U15.2(GND) U24.2(GND) U24.25(CPAD) U25.2(GND) U26.2(GND) U27.2(GND) U28.2(GND) U33.2(GND) U34.4(GND) U36.4(GND) U41.4(GND) U46.3(GND) X1.2 X1.4 ; also on sheet 8 9 10 11 12 13
V1V5_EN: R5.1 R7.1 U12.4(EN)
VCC_1V5: C20.1 C93.1 C94.1 C95.1 P8.6(+1.5V/NC) P8.28(+1.5V/NC) P8.48(+1.5V/NC) R14.2 U12.7(Vout1) U12.8(Vout2)
VCC_3V3: C1.1 C19.1 C23.2 C24.2 C25.2 C26.2 C27.1 C28.1 C32.1 C33.1 C34.1 C35.1 C36.1 C37.1 C51.1 C52.1 C64.1 C71.1 C72.1 C74.1 C127.2 C143.1 C146.1 C148.1 C149.1 C152.2 C200.1 C202.2 C244.2 C250.1 C271.2 C272.2 C291.1 FB4.2 L5.1 L8.1 P1.55 P4.P4(VDD) P5.P12(LED1_A) P6.P12(LED1_A) P8.2(+3.3V_AUX) P8.39(3.3V_AUX) P8.41(3.3V_AUX) P8.52(+3.3V_AUX) P12.20 P13.2 P14.20 P22.2(+3.3V) P22.4(+3.3V) P22.12(+3.3V) P22.14(+3.3V) P22.16(+3.3V) P22.18(+3.3V) P22.70(+3.3V) P22.72(+3.3V) P22.74(+3.3V) P25.20 R3.1 R4.1 R7.2 R9.1 R15.1 R38.1 R40.1 R44.1 R76.2 R160.1 R162.2 R164.2 R168.2 R171.2 R173.1 R188.1 R189.1 R229.1 R271.1 R273.1 U1.1(VDD1) U1.5(VDD2) U1.11(VDD3) U1.18(VDD4) U1.24(VDD5) U14.29(DVDD33) U15.6(IN) U25.3(VCCA) U27.5(VBUS) U28.5(VBUS) U33.5(VBUS) U34.9(VCC) U36.9(VCC) ; also on sheet 8 9 10 11 12 13
VCC_5V0: C55.1 C56.1 C87.1 C92.1 C195.2 C230.2 L9.1 L34.1 R52.1 R53.1 R191.1 U5.1(IN) U6.1(IN) U41.6(Vin) U41.7(Vin) U46.5(VCC) ; also on sheet 9 11 12 13
VCC_RTC: P1.93 ; also on sheet 12
ADC_IN0: P9.1 ; also on sheet 13
ADC_IN1: P9.3 ; also on sheet 13
ADC_IN2: P9.5 ; also on sheet 13
ADC_IN3: P9.7 ; also on sheet 13
ADC_IN4: P9.11 ; also on sheet 13
ADC_IN5: P9.13 ; also on sheet 13
ADC_IN6: P9.15 ; also on sheet 13
ADC_IN7: P9.17 ; also on sheet 13
ALT_BOOT#: E3.1 P1.90 SW2.2 SW2.4
CAN2_RX: P1.49 ; also on sheet 13
CAN2_TX: P1.33 ; also on sheet 13
COLD_RESET_IN: P1.2 SW3.2 SW3.4 ; also on sheet 13
CON_UART_RXD: U24.21(TXD) U25.8(B1)
CON_UART_TXD: U24.20(RXD) U25.1(B2)
DSI1_CN: L61.2 P12.5
DSI1_CP: L61.1 P12.3
DSI1_N0: L59.2 P12.6
DSI1_N1: L60.2 P12.11
DSI1_N2: L62.2 P12.12
DSI1_N3: L63.2 P12.18
DSI1_P0: L59.1 P12.4
DSI1_P1: L60.1 P12.9
DSI1_P2: L62.1 P12.10
DSI1_P3: L63.1 P12.16
DSI_BCKLIGHT_FB: D7.2(ANODE) R41.2 U15.3(FB)
DSI_DISP_RESET: P12.17 R81.1 ; also on sheet 13
DSI_LED_A: C245.2 C278.1 D2.CATHODE D7.1(CATHODE) P12.19 U15.5(OVP)
DSI_LED_K: C245.1 P12.15 R39.1 R41.1
DSI_WLD_SW: D2.ANODE L8.2 U15.1(LX)
ENET1_MDC: P2.68 U14.13(MDC)
ENET1_MDIO: P2.70 R106.1 U14.14(MDIO)
ENET2_nRST: R99.1 R168.1 U14.12(~{PHYRST})
ENET2_RD0: P2.41 R138.1 R258.2 U14.25(RXD0/RXDLY)
ENET2_RD1: P2.43 R170.1 R232.1 U14.24(RXD1/TXDLY)
ENET2_RD2: P2.45 R128.2 R265.1 U14.23(RXD2/PLLOFF)
ENET2_RD3: P2.47 R251.1 R263.1 U14.22(RXD3/PHYAD0)
ENET2_RX_CTL: P2.53 R233.1 R262.1 U14.26(RXCTL/PHYAD2)
ENET2_RXC: P2.55 R163.2 R238.1
ENET2_TD0: P2.59 U14.18(TXD0)
ENET2_TD1: P2.61 U14.17(TXD1)
ENET2_TD2: P2.63 U14.16(TXD2)
ENET2_TD3: P2.65 U14.15(TXD3)
ENET2_TX_CTL: P2.67 U14.19(TXCTL)
ENET2_TXC: C279.1 P2.69 U14.20(TXC)
ETH1_CT1: C60.1 C61.1 P5.P5(CT)
ETH1_CT2: C66.1 P5.P6(CT)
ETH1_GREEN_LED_CAT: P5.P11(LED1_C) R46.1
ETH1_LED0/CFG_EXT: P2.86 R46.2
ETH1_LED2/CFG_LDO1: P2.75 P5.P14(LED2_A)
ETH1_MDI0N: P2.73 P5.P2(MDI0-)
ETH1_MDI0P: P2.74 P5.P1(MDI0+)
ETH1_MDI1N: P2.80 P5.P4(MDI1-)
ETH1_MDI1P: P2.78 P5.P3(MDI1+)
ETH1_MDI2N: P2.81 P5.P8(MDI2-)
ETH1_MDI2P: P2.79 P5.P7(MDI2+)
ETH1_MDI3N: P2.85 P5.P10(MDI3-)
ETH1_MDI3P: P2.84 P5.P9(MDI3+)
ETH1_YELLOW_LED_CAT: P5.P13(LED2_C) R47.1
ETH2_1V0: C248.2 C249.2 R177.1 R178.1 U14.30(LDO_OUT)
ETH2_AVDD10: C138.2 C139.2 C269.2 C270.2 R177.2 U14.3(AVDD10_1) U14.8(AVDD10_2) U14.38(AVDD10_3)
ETH2_AVDD33: C273.2 C274.2 FB4.1 U14.11(AVDD33_1) U14.40(AVDD33_2)
ETH2_CT1: C69.1 C70.1 P6.P5(CT)
ETH2_CT2: C78.1 P6.P6(CT)
ETH2_DVDD10: C267.2 C268.2 R178.2 U14.21(DVDD10)
ETH2_DVDD_RG: C275.2 C276.2 R106.2 R128.1 R162.1 R170.2 R233.2 R251.2 R258.1 U14.28(DVDD_RG)
ETH2_GREEN_LED_CAT: P6.P11(LED1_C) R101.1
ETH2_LED0/CFG_EXT: R101.2 R267.1 R271.2 U14.32(LED0/CFG_EXT)
ETH2_LED1/CFG_LDO0: R272.1 U14.33(LED1/CFG_LDO0)
ETH2_LED2/CFG_LDO1: P6.P14(LED2_A) R269.1 R273.2 U14.34(LED2/CFG_LDO1)
ETH2_MDI0N: P6.P2(MDI0-) U14.2(MDIN0)
ETH2_MDI0P: P6.P1(MDI0+) U14.1(MDIP0)
ETH2_MDI1N: P6.P4(MDI1-) U14.5(MDIN1)
ETH2_MDI1P: P6.P3(MDI1+) U14.4(MDIP1)
ETH2_MDI2N: P6.P8(MDI2-) U14.7(MDIN2)
ETH2_MDI2P: P6.P7(MDI2+) U14.6(MDIP2)
ETH2_MDI3N: P6.P10(MDI3-) U14.10(MDIN3)
ETH2_MDI3P: P6.P9(MDI3+) U14.9(MDIP3)
ETH2_RSET: R124.2 U14.39(RSET)
ETH2_YELLOW_LED_CAT: P6.P13(LED2_C) R133.1
FB_LDO_1V5: R8.1 R14.1 U12.6(ADJ)
GBEPHY2_CLK_XIN: C81.2 U14.36(XTAL_IN) X1.3
GBEPHY2_CLK_XOUT: C83.2 U14.37(XTAL_OUT/_EXT_CLK) X1.1
GPIO1_IO11: P1.95 ; also on sheet 13
GPIO1_IO14: P1.98 ; also on sheet 13
GPIO4_IO28_1V8: P2.49 ; also on sheet 10
GPIO4_IO29_1V8: P2.52 ; also on sheet 10
GPIO_ENET2_INT: P2.60 R122.2
GPIO_ENET2_nRST: P2.76 R99.2
GPIO_IO08: P1.97 ; also on sheet 13
GPIO_IO18: P1.32 R44.2 R207.1
GPIO_IO19: P1.34 P13.5 U33.4(IO3)
GPIO_IO22: P1.79 ; also on sheet 9
GPIO_IO32: P2.90 ; also on sheet 13
GPIO_IO35: P1.85 R15.2 R16.2
HOST1_USB_DN: J3.2(DN) L11.4
HOST1_USB_DP: J3.3(DP) L11.3
HOST2_USB_DN: J2.2(D-) L17.4
HOST2_USB_DP: J2.3(D+) L17.3
I2C3_SCL: P1.94 P13.1 R3.2 R36.1 U33.1(IO1) ; also on sheet 9 13
I2C3_SDA: P1.91 P13.3 R4.2 R37.1 U33.3(IO2) ; also on sheet 9 13
I2C4_SCL: P1.53 R189.2 ; also on sheet 8
I2C4_SDA: P1.51 R173.2 ; also on sheet 8
I2C8_SCL: P1.100 R188.2 ; also on sheet 8 13
I2C8_SDA: P1.96 R160.2 ; also on sheet 8 13
JTAG_TCK: P1.73 ; also on sheet 13
JTAG_TDI: P1.71 ; also on sheet 13
JTAG_TDO: P1.67 ; also on sheet 13
JTAG_TMS: P1.65 ; also on sheet 13
LVDS0_CLK_N: L13.4 P1.82
LVDS0_CLK_P: L13.3 P1.80
LVDS0_CLKN: L13.1 P14.5
LVDS0_CLKP: L13.2 P14.3
LVDS0_COMP: C58.1 U5.5(COMP)
LVDS0_D0_N: L2.4 P1.44
LVDS0_D0_P: L2.3 P1.42
LVDS0_D1_N: L1.4 P1.48
LVDS0_D1_P: L1.3 P1.46
LVDS0_D2_N: L7.4 P1.52
LVDS0_D2_P: L7.3 P1.50
LVDS0_D3_N: L12.4 P1.58
LVDS0_D3_P: L12.3 P1.56
LVDS0_DISP_RESET: P14.17 R83.1 ; also on sheet 13
LVDS0_LED_NEG: C85.1 P14.15 R65.1 R66.1 U5.6(FB)
LVDS0_LED_POS: C57.1 C85.2 D11.CATHODE P14.19
LVDS0_N0: L2.1 P14.6
LVDS0_N1: L1.1 P14.11
LVDS0_N2: L7.1 P14.12
LVDS0_N3: L12.1 P14.18
LVDS0_P0: L2.2 P14.4
LVDS0_P1: L1.2 P14.9
LVDS0_P2: L7.2 P14.10
LVDS0_P3: L12.2 P14.16
LVDS0_RESET: R63.1 R65.2 R66.2
LVDS0_WLD_SW: D11.ANODE L9.2 U5.3(SW)
LVDS1_CLK_N: L33.4 P2.58
LVDS1_CLK_P: L33.3 P2.56
LVDS1_CLKN: L33.1 P25.5
LVDS1_CLKP: L33.2 P25.3
LVDS1_COMP: C97.1 U6.5(COMP)
LVDS1_CTRL: R53.2 R56.1 R57.1 U6.2(CTRL)
LVDS1_D0_N: L3.4 P2.14
LVDS1_D0_P: L3.3 P2.12
LVDS1_D1_N: L4.4 P2.20
LVDS1_D1_P: L4.3 P2.18
LVDS1_D2_N: L6.4 P2.26
LVDS1_D2_P: L6.3 P2.24
LVDS1_D3_N: L10.4 P2.50
LVDS1_D3_P: L10.3 P2.48
LVDS1_DISP_RESET: P25.17 R84.1 ; also on sheet 13
LVDS1_LED_NEG: C91.1 P25.15 R58.1 R59.1 U6.6(FB)
LVDS1_LED_POS: C91.2 C96.1 D12.CATHODE P25.19
LVDS1_N0: L3.1 P25.6
LVDS1_N1: L4.1 P25.11
LVDS1_N2: L6.1 P25.12
LVDS1_N3: L10.1 P25.18
LVDS1_P0: L3.2 P25.4
LVDS1_P1: L4.2 P25.9
LVDS1_P2: L6.2 P25.10
LVDS1_P3: L10.2 P25.16
LVDS1_RESET: R58.2 R59.2 R60.1
LVDS1_WLD_SW: D12.ANODE L34.2 U6.3(SW)
MIPI_CSI1_CLK_N: P2.2 ; also on sheet 8
MIPI_CSI1_CLK_P: P2.4 ; also on sheet 8
MIPI_CSI1_D0_N: P2.6 ; also on sheet 8
MIPI_CSI1_D0_P: P2.8 ; also on sheet 8
MIPI_CSI1_D1_N: P2.31 ; also on sheet 8
MIPI_CSI1_D1_P: P2.33 ; also on sheet 8
MIPI_CSI1_D2_N: P2.25 ; also on sheet 8
MIPI_CSI1_D2_P: P2.27 ; also on sheet 8
MIPI_CSI1_D3_N: P2.35 ; also on sheet 8
MIPI_CSI1_D3_P: P2.37 ; also on sheet 8
MIPI_DSI_CLK_N: L61.3 ; also on sheet 8
MIPI_DSI_CLK_P: L61.4 ; also on sheet 8
MIPI_DSI_D0_N: L59.3 ; also on sheet 8
MIPI_DSI_D0_P: L59.4 ; also on sheet 8
MIPI_DSI_D1_N: L60.3 ; also on sheet 8
MIPI_DSI_D1_P: L60.4 ; also on sheet 8
MIPI_DSI_D2_N: L62.3 ; also on sheet 8
MIPI_DSI_D2_P: L62.4 ; also on sheet 8
MIPI_DSI_D3_N: L63.3 ; also on sheet 8
MIPI_DSI_D3_P: L63.4 ; also on sheet 8
MIPI_DSICSI_CLK_N: P2.21 ; also on sheet 8
MIPI_DSICSI_CLK_P: P2.23 ; also on sheet 8
MIPI_DSICSI_D0_N: P2.1 ; also on sheet 8
MIPI_DSICSI_D0_P: P2.3 ; also on sheet 8
MIPI_DSICSI_D1_N: P2.15 ; also on sheet 8
MIPI_DSICSI_D1_P: P2.17 ; also on sheet 8
MIPI_DSICSI_D2_N: P2.5 ; also on sheet 8
MIPI_DSICSI_D2_P: P2.7 ; also on sheet 8
MIPI_DSICSI_D3_N: P2.11 ; also on sheet 8
MIPI_DSICSI_D3_P: P2.13 ; also on sheet 8
MODEM_AUX: C73.1 P8.24(+3.3V_AUX)
MODEM_RF_KILL#: P8.20(W_DISABLE#) R38.2 ; also on sheet 13
mPCIE_CLKN: P8.11(REFCLK-/UART_CTS) R21.1 R28.2
mPCIE_CLKP: P8.13(REFCLK+/UART_RTS) R22.1 R27.2
MUX_USB1_DN: L11.1 U34.7(HSD1-)
MUX_USB1_DP: L11.2 U34.1(HSD1+)
MUX_USB1_OE#: R172.2 U34.8(\\~{O}E)
MUX_USB2_DN: L17.1 U36.7(HSD1-)
MUX_USB2_DP: L17.2 U36.1(HSD1+)
MUX_USB2_OE#: R209.2 U36.8(\\~{O}E)
MUX_USB_SDP_DN: L16.1 U34.6(HSD2-)
MUX_USB_SDP_DP: L16.2 U34.2(HSD2+)
PCIE1_CLKIN_N: P2.44 R19.1 R31.2
PCIE1_CLKIN_P: P2.42 R20.1 R29.2
PCIE1_RST: P22.50(PERST#) R16.1
PCIE1_RX0_N: P2.30 P22.41(SATA_RXP/PERN0)
PCIE1_RX0_P: P2.32 P22.43(SATA_RXN/PERP0)
PCIE1_TX0_N: P2.36 P22.47(SATA_TXN/PETN0)
PCIE1_TX0_P: P2.38 P22.49(SATA_TXP/PETP0)
PCIE2_CLKIN_N: P1.31 R23.1 R26.2
PCIE2_CLKIN_P: P1.29 R24.1 R25.2
PCIE2_RST: P8.22(PERST#) R207.2
PCIE2_RX0_N: P1.47 P8.23(PER_N0/NC)
PCIE2_RX0_P: P1.45 P8.25(PER_P0/NC)
PCIE2_TX0_N: P1.41 P8.31(PET_N0/NC)
PCIE2_TX0_P: P1.39 P8.33(PET_P0/NC)
PCIE_CLKM_IREF: R43.2 U1.26(Iref)
PCIE_CLKM_OEINV: R40.2 U1.25(OE_INV)
PCIE_CLKM_SCLK: R36.2 U1.13(SCLK)
PCIE_CLKM_SDA: R37.2 U1.14(SDA)
PCIE_CLKOUT_N: P1.25 U1.3(SEC#)
PCIE_CLKOUT_P: P1.23 U1.2(SRC)
PCIE_NVME_CLKN: P22.53(PECLKN) R17.1 R33.2
PCIE_NVME_CLKP: P22.55(PECLKP) R18.1 R32.2
PCIE_P0_CLKN: R26.1 U1.7(OUT0#)
PCIE_P0_CLKP: R25.1 U1.6(OUT0)
PCIE_P1_CLKN: R28.1 U1.10(OUT1#)
PCIE_P1_CLKP: R27.1 U1.9(OUT1)
PCIE_P2_CLKN: R31.1 U1.19(OUT2#)
PCIE_P2_CLKP: R29.1 U1.20(OUT2)
PCIE_P3_CLKN: R33.1 U1.22(OUT3#)
PCIE_P3_CLKP: R32.1 U1.23(OUT3)
PDM_BIT_STREAM0: P9.4 R57.2
PHY2_INT: R122.1 R164.1 U14.31(~{INT}/~{PME})
PHY2_RXC: R163.1 U14.27(RXC/PHYAD1)
PMIC_ON_REQ: P1.68 ; also on sheet 11 13
PMIC_STBY_REQ: P1.66 ; also on sheet 11 13
POR_B_3V3: P2.66 ; also on sheet 10
PWM1: P1.35 R229.2 U15.4(EN/PWM)
PWM2: P1.37 R52.2 U5.2(CTRL)
PWM3: P1.99 R56.2
PWRBTN: P2.64 SW4.2 SW4.4
SAI3_MCLK: P1.30 ; also on sheet 9
SAI3_RXD: P1.28 ; also on sheet 9
SAI3_TXC: P1.36 ; also on sheet 9
SAI3_TXD: P1.26 ; also on sheet 9
SAI3_TXFS: P1.38 ; also on sheet 9
SD2_CLK: P2.96 P4.P5(CLK) U27.3(IO2)
SD2_CMD: P2.100 P4.P3(CMD) U28.6(IO4)
SD2_DATA0: P2.97 P4.P7(DAT0) U27.1(IO1)
SD2_DATA1: P2.99 P4.P8(DAT1) U27.6(IO4)
SD2_DATA2: P2.94 P4.P1(DAT2) U28.1(IO1)
SD2_DATA3: P2.98 P4.P2(DAT3) U28.4(IO3)
SD2_nCD: P2.92 P4.P9(CD#) R9.2
SDP_BOOT#: E4.1 P2.88 SW5.2 SW5.4
SERIAL_VBUSIN: C142.1 P3.1(VBUS) U24.7(REGIN) U24.8(VBUS) U26.5(VBUS)
SIM_CLK: P7.3(CLK) P8.12(UIM_CLK)
SIM_IO: P7.7(IO) P8.10(UIM_DATA)
SIM_RST: P7.2(RST) P8.14(UIM_RESET)
SIM_VCC: C231.2 P7.1(VCC) P8.8(UIM_PWR)
SIM_VPP: P7.6(VPP) P8.16(UIM_VPP/GPIO42)
SPDIF_TX: P1.81 ; also on sheet 13
SPI7_CS0: P2.91 ; also on sheet 13
SPI7_MISO: P2.89 ; also on sheet 13
SPI7_MOSI: P2.95 ; also on sheet 13
SPI7_SCLK: P2.93 ; also on sheet 13
TOUCH_RESET: P13.7 R82.1 U33.6(IO4) ; also on sheet 13
UART1_RXD: P1.76 U25.5(A1)
UART1_TXD/BT_MODE0: P1.74 U25.4(A2)
UART2_CTS#: P1.70 ; also on sheet 13
UART2_RTS#: P1.92 ; also on sheet 13
UART2_RXD: P1.84 ; also on sheet 13
UART2_TXD/BT_MODE1: P1.86 ; also on sheet 13
UART3_RX: P1.19 ; also on sheet 13
UART3_TX: P1.72 ; also on sheet 13
USB1_DN: P1.14 U34.5(D-)
USB1_DP: P1.12 U34.3(D+)
USB1_RX0_N: L15.2 P1.8
USB1_RX0_P: L15.1 P1.6
USB1_SEL: R30.1 R169.1 U34.10(SEL)
USB1_SSRXN: J3.5(SSRXN) L15.3
USB1_SSRXP: J3.6(SSRXP) L15.4
USB1_SSTXN: J3.8(SSTXN) L14.3
USB1_SSTXP: J3.9(SSTXP) L14.4
USB1_TX0_N: L14.2 P1.18
USB1_TX0_P: L14.1 P1.16
USB1_VBUS_DET: P1.24 U46.4(A+B)
USB2_DN: P1.5 U36.5(D-)
USB2_DP: P1.3 U36.3(D+)
USB2_MINIPCI_DN: P8.36(USB_D-) U36.6(HSD2-)
USB2_MINIPCI_DP: P8.38(USB_D+) U36.2(HSD2+)
USB2_SEL: E1.1 R171.1 U36.10(SEL)
USB2_VBUS_DET: P1.1 R218.2 R225.2
USB_OC_LIMIT: R193.1 U41.8(IP)
USB_PWR_EN: R191.2 U41.5(EN) ; also on sheet 13
USBSD_VBUS: C182.2 C194.1 P21.1(VBUS) R169.2 R194.2
USBSD_VBUS_R: R194.1 U46.1(A)
USBSDM_DN: L16.4 P21.2(D-)
USBSDM_DP: L16.3 P21.3(D+)
USBSERIAL_3V45: C140.1 C141.1 C144.1 R134.1 U24.5(VIO) U24.6(VDD) U25.7(VCCB)
USBSERIAL_DN: P3.2(D-) U24.4(DN) U26.6(IO4)
USBSERIAL_DP: P3.3(D+) U24.3(DP) U26.1(IO1)
USBSERIAL_nRST: R134.2 U24.9(RST#)
USBSERIALEN: R76.1 U25.6(OE)
V_SOM: C2.1 C3.1 C4.1 C5.1 C6.1 C7.1 C8.1 C9.1 C10.1 C11.1 C12.1 C13.1 C14.1 C15.1 C16.1 C17.1 C18.1 P1.11 P1.27 P1.43 P1.57 P1.69 P1.83 P2.9 P2.19 P2.29 P2.39 P2.57 P2.71 P2.87 R5.2 U12.1(Vin1) U12.2(Vin2) ; also on sheet 11 12
XSPI_CLK: P9.10 ; also on sheet 10
XSPI_DATA0: P9.22 ; also on sheet 10
XSPI_DATA1: P9.24 ; also on sheet 10
XSPI_DATA2: P9.28 ; also on sheet 10
XSPI_DATA3: P9.30 ; also on sheet 10
XSPI_DATA4: P9.32 ; also on sheet 10
XSPI_DATA5: P9.36 ; also on sheet 10
XSPI_DATA6: P9.38 ; also on sheet 10
XSPI_DATA7: P9.40 ; also on sheet 10
XSPI_DQS: P9.14 ; also on sheet 10
XSPI_SS0_B: P9.20 ; also on sheet 10
XSPI_SS1_B: P9.16 ; also on sheet 10

Not connected (* = marked no-connect by the designer): P1 7* 9* 13* 15* 17* 21* 22* 59* 60* 61* 62* 63* 75* 77* 87* 89*; P2 51* 62* 77* 83*; P3 4(ID)* 10(NC1)* 11(NC2)*; P7 4(RSVD4)* 8(RSVD8)*; P8 1(WAKE#/MIC1P)* 3(COEX1/MIC1N)* 5(COEX2/EAR1P)* 7(CLKREQ#/EAR1N)* 17(RSVD/UART_RXD)* 19(RSVD/UART_TXD)* 30(GPIO9/SMB_CLK)* 32(GPIO6/SMB_DATA)* 42(LED_WWAN#)* 44(LED_WLAN#/UART_RI)* 45(RSVD/PCM_CLK)* 46(LED_WPAN#/UART_DTR)* 47(RSVD/PCM_OUT)* 49(RSVD/PCM_IN)* 51(RSVD/PCM_SYNC)*; P9 2* 6* 21* 25* 27* 31* 33* 37* 39*; P13 4* 6*; P21 4(ID)*; P22 5(PERN3)* 6(RSVD)* 7(PERP3)* 8(RSVD)* 10(DAS/DSS#)* 11(PETN3)* 13(PETP3)* 17(PERN2)* 19(PERP2)* 20(RSVD)* 22(RSVD)* 23(PETN2)* 24(RSVD)* 25(PETP2)* 26(RSVD)* 28(RSVD)* 29(PERN1)* 30(RSVD)* 31(PERP1)* 32(RSVD)* 34(RSVD)* 35(PETN1)* 36(RSVD)* 37(PETP1)* 38(DEV_SLP)* 40(SMB_CLK(1.8V))* 42(SMB_DATA(1.8V))* 44(ALERT#)* 46(RSVD)* 48(RSVD)* 52(CLKREQ#)* 54(PEWAKE#)* 56(RSVD)* 58(RSVD)* 67(RSVD)* 68(SUSCLK)* 69(PEDET)*; U12 3(PGOOD)*; U14 35(CLKOUT)*; U24 1(RI)* 10(NC)* 11(GPIO3)* 12(GPIO2)* 13(GPIO1)* 14(GPIO0)* 15(SUSPEND#)* 16(VPP)* 17(SUSPEND)* 18(CTS)* 19(RTS)* 22(DSR)* 23(DTR)* 24(DCD)*; U26 3(IO2)* 4(IO3)*; U27 4(IO3)*; U28 3(IO2)*; U41 1(FLG)*

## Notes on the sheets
sheet 1
- SB-UCMIMX95
- Page
- Description
- 01
- Index and Block Diagram
- 02
- SOM connectors
- 03
- Console, GbE, micro-SD
- 04
- Carrier-board Ethernet
- 05
- USB #1 and SDP
- 06
- USB #2 and PCIe
- 07
- LVDS and MPI-DSI
- 08
- MIPI-CSI
- 09
- Audio codec
- 10
- Octal SPI flash
- 11
- I/O headers, JTAG, GPIO exp.
- 12
- LEDs
- 13
- Power
- 14
- DC input and spacers
- CH #
- I2C devices
- I2C3
- EEPROM, PCA9500, codec, touch,
- I2C4
- Camera
- I2C8
- Camera, header
sheet 2
- V-SOM decoupling capacitors
- EXT_ENET
- UART3: CORTEX-M7 DEBUG
- Place close to SOM connectors
- main console
- UART2: CORTEX-M33 DEBUG
- Buttons
- ALT_BOOT jumper
- SDP_BOOT jumper
- I2C pull-up resistors
sheet 3
- Serial debug console
- UCM RX <--> CP2104 TX
  UCM RT <--> CP2104 RX
- SERIAL CONSOLE PORT
  (microUSB2.0 Type B)
  UART over USB
- A55 core debug
- O
- O
- SILKSCREEN:
  Serial Console USB to UART1
- UCM Ethernet connector
- Micro-SD socket (bootable)
- SILKSCREEN:
  ETH1
- SILKSCREEN:
  MicroSD (SD2)
- 100 Ohm
- 100 Ohm
- 100 Ohm
- 100 Ohm
sheet 4
- Carrier-board Ethernet PHY
- Power-on strap pins CFG
- RGMII Power Source
- CFG_EXT
- CFG_LDO[1:0]
- External 3.3V
- 1
- 00
- External 1.8V
- 1
- 10
- Internal 1.8V
- 0
- 10
- DNP
- CFG_EXT
- DNP
- CFG_LDO1
- CFG_LDO0
- CONFIG PINS
- Active low
- Active low
- Active high
- DNP
- DNP
- DNP
- PLLOFF
- TXDLY
- RXDLY
- DNP
- PHYADDRESS2
- DNP
- PHYADDRESS1
- PHYADDRESS0
- Carrier-board Ethernet
  connector
- PHY ADDRESS = [1,0,0]
- PHY support addresses from 00001 to 00111.
  PHY address 0 is a broadcast from the MAC
- PLLOFF: Pull-up to disable PLL @ ALDPS mode.
- Enable internal delays
- TX delay is disabled
  RX delay is enabled
sheet 5
- USB #1 SDP mux (USB2 signals only)
- USB #1 connector
- 90 ohm
- # 90-Ohm differential pairs
- # 90-Ohm differential pairs
- SDP connector
- # 90-Ohm diff pairs
- Assembly ACAP to L23
- Serial Download mode
  (microUSB2.0 Type B)
- USB VBUS
- USB power
- Cur. limit =
  2.1 A/ 3ports
sheet 6
- USB #2 mux
- PCIe clock multiplier
- # 90-Ohm differential pairs
- Close:  for USB conn.
  Open: for miniPCIe socket
- USB #2 connector
- DNP
- DNP
- Adrr = DCh - DDh
- 90 ohm
- Mini-PCIe socket
- M.2 for NVME
- int. PU
- 1V5
- DNP
- Vout=Vfb*(1+Rt/Rb)=0.8*(1+9.1/10)=1.528V
sheet 7
- LVDS0 connector
- LVDS0 panel back-light
- DNP
- # 100-Ohm diff pairs
- # 100-Ohm diff pairs
- LVDS1 panel back-light
- LVDS1 connector
- DNP
- DNP
- MIPI-DSI panel back-light
- # 100-Ohm diff pairs
- # 100-Ohm diff pairs
- Typical LED configuration: Two parallel chains of 6 serially connected LEDs
- MIPI-DSI connector
- DNP
- # 100-Ohm diff pairs
- Touch-screen
- # 100-Ohm diff pairs
